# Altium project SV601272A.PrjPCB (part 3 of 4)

## Sheet SV601272A-Controller1.SchDoc: Controller
size 431 x 279 mm; Date: Not shown in title block; ApprovedBy: Not shown in title block; CheckedBy: Not shown in title block; Author: Not shown in title block; CompanyName: Not shown in title block; Engineer: Not shown in title block; Organization: Not shown in title block; Address1: Not shown in title block; Address2: Not shown in title block; Address3: Not shown in title block; Address4: Not shown in title block; DocumentNumber: 4; Revision: Use project parameter SCH_Rev; SheetNumber: 4; SheetTotal: 11; PageSetup: Record=PageOptions¦CenterHorizontal=True¦CenterVertical=True¦PrintScale=1.00¦XCorrection=1.00¦YCorrection=1.00¦PrintKind=0¦BorderSize=5000000¦LeftOffset=0¦BottomOffset=0¦Orientation=2¦PaperLength=1000¦PaperWidth=1000¦Scale=100¦PaperSource=15¦PrintQuality=600¦MediaType=1¦DitherType=10¦PaperKind=Letter¦PrintScaleMode=1
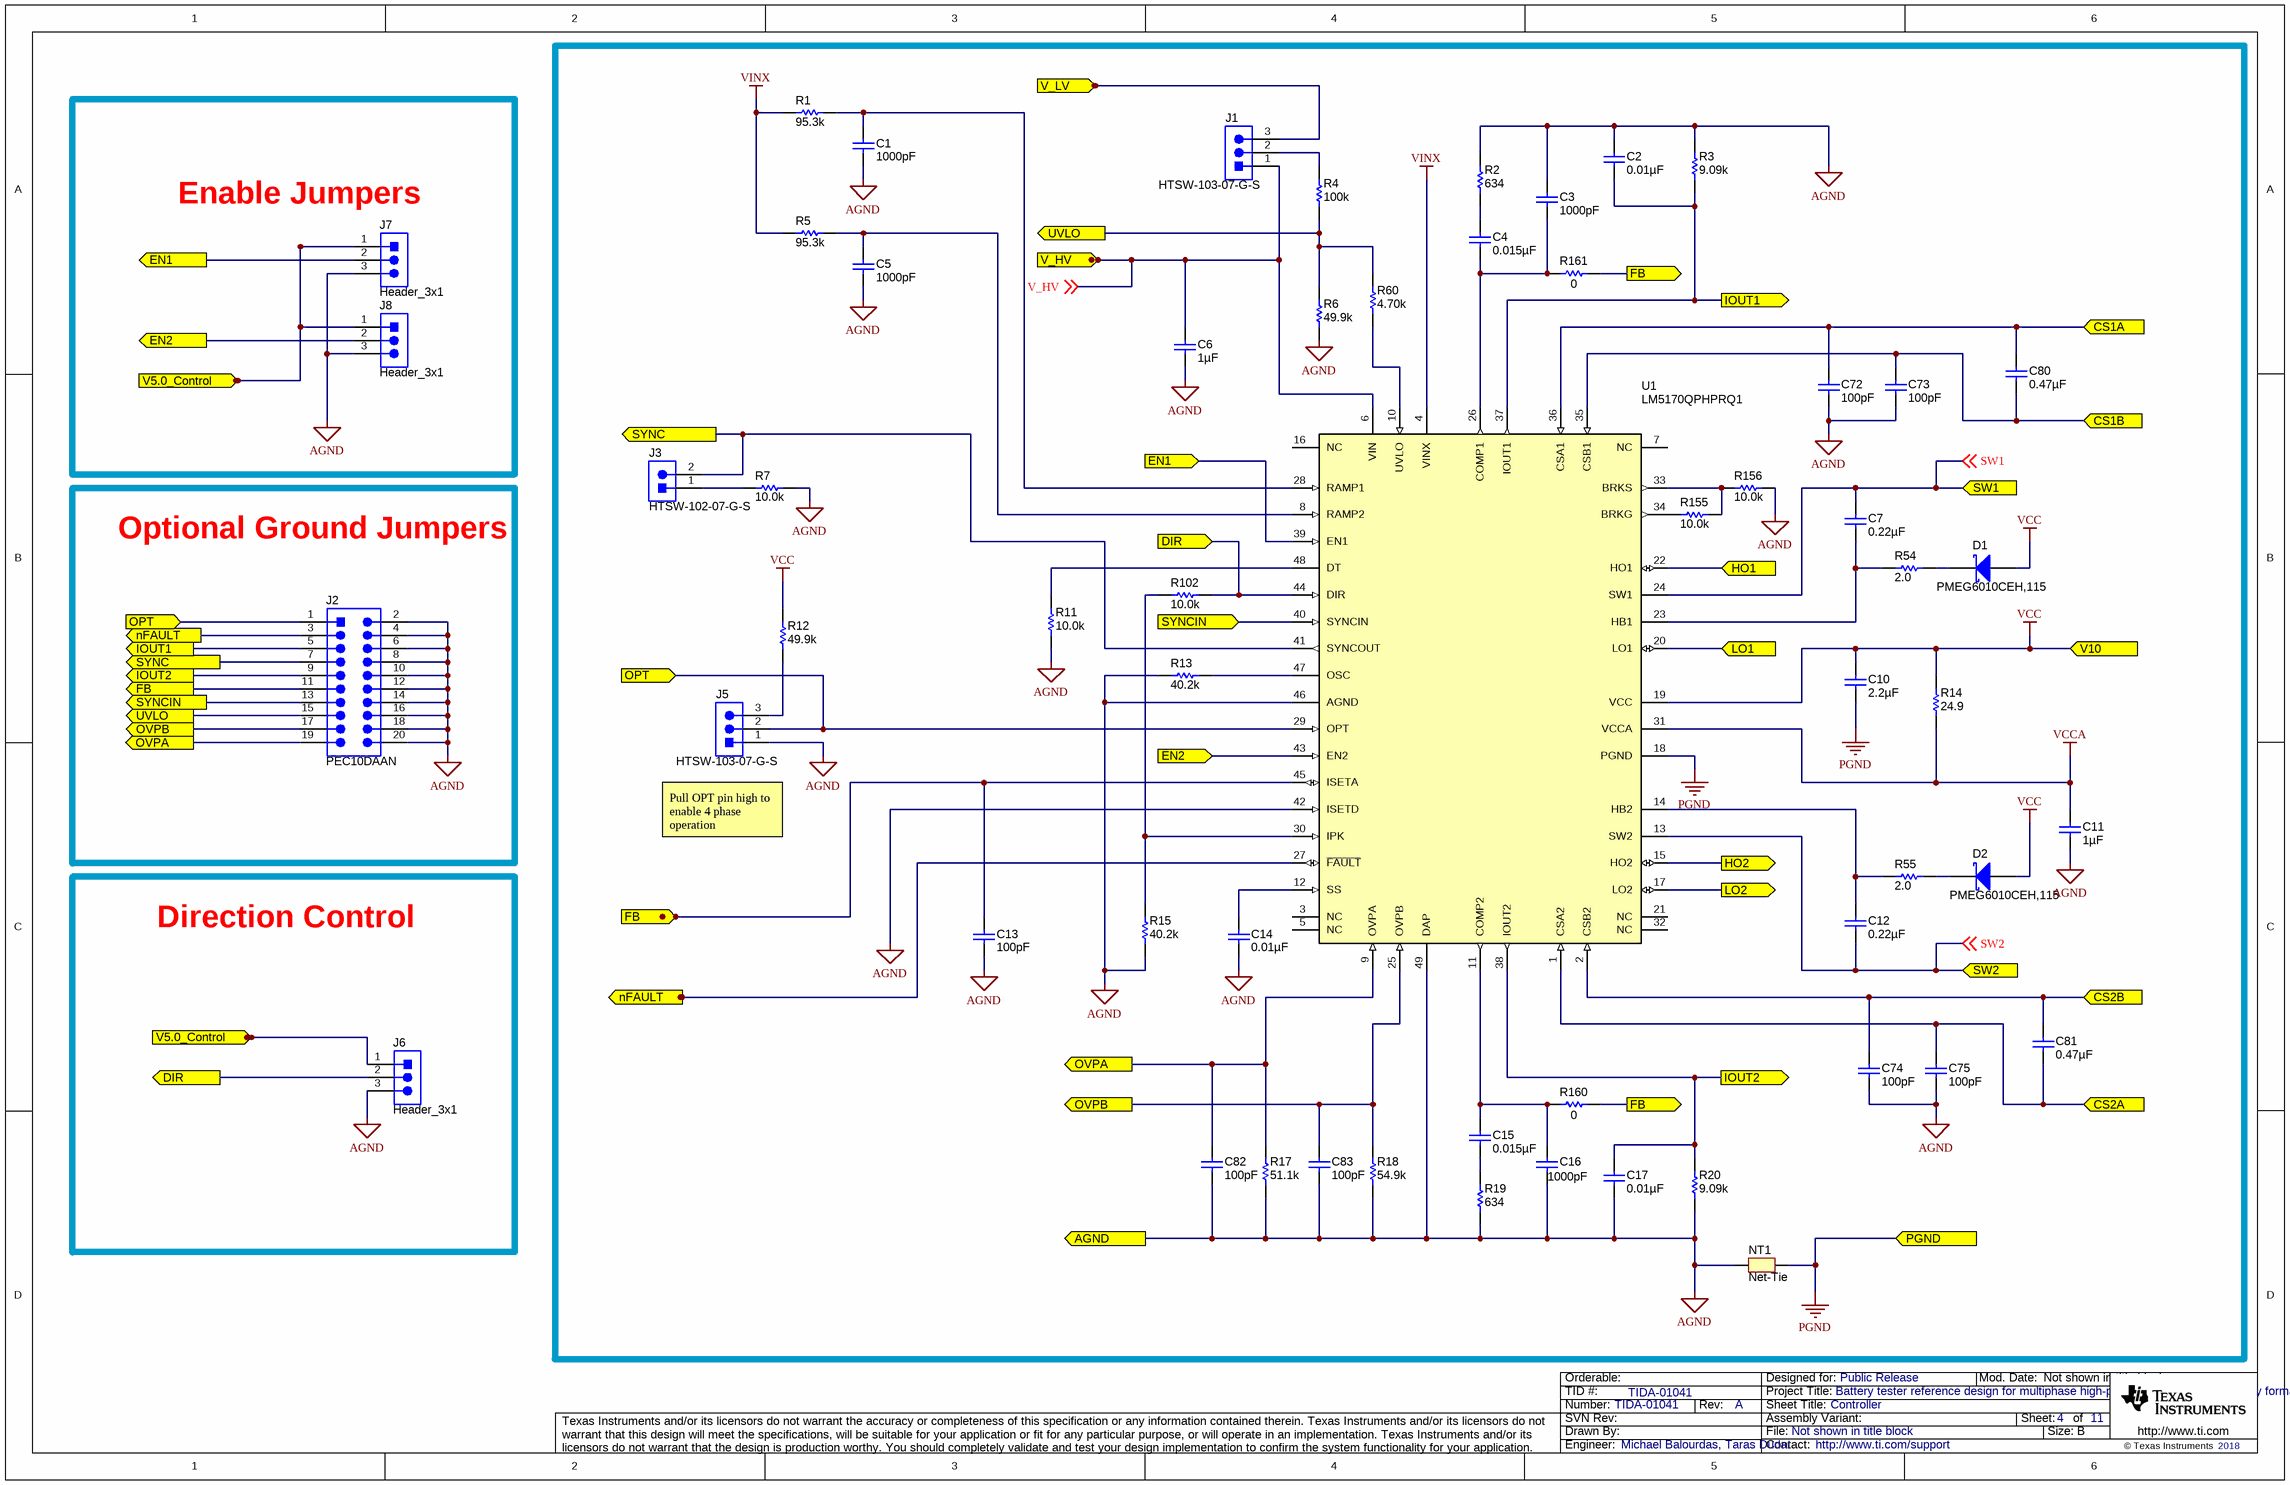
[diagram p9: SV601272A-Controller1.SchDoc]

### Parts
C1  ValueDisplayed: 1000pF  [0603L]  (hidden comment: C1608C0G2A102J080AA)
C2  ValueDisplayed: 0.01µF  [0603L]  (hidden comment: 06031C103KAT2A)
C3  ValueDisplayed: 1000pF  [0603L]  (hidden comment: C1608C0G2A102J080AA)
C4  ValueDisplayed: 0.015µF  [0603L]  (hidden comment: GRM188R71E153KA01D)
C5  ValueDisplayed: 1000pF  [0603L]  (hidden comment: C1608C0G2A102J080AA)
C6  ValueDisplayed: 1µF  [0805_HV]  (hidden comment: C2012X7S2A105K125AB)
C7  ValueDisplayed: 0.22µF  [0603L]  (hidden comment: C1608X7R1H224K080AB)
C10  ValueDisplayed: 2.2µF  [0805_HV]  (hidden comment: C2012X7R1C225K125AB)
C11  ValueDisplayed: 1µF  [0603L]  (hidden comment: GRM188R71E105KA12D)
C12  ValueDisplayed: 0.22µF  [0603L]  (hidden comment: C1608X7R1H224K080AB)
C13  ValueDisplayed: 100pF  [0603L]  (hidden comment: C0603C101J5GACTU)
C14  ValueDisplayed: 0.01µF  [0603L]  (hidden comment: 06031C103KAT2A)
C15  ValueDisplayed: 0.015µF  [0603L]  (hidden comment: GRM188R71E153KA01D)
C16  ValueDisplayed: 1000pF  [0603L]  (hidden comment: C1608C0G2A102J080AA)
C17  ValueDisplayed: 0.01µF  [0603L]  (hidden comment: 06031C103KAT2A)
C72  ValueDisplayed: 100pF  [0603L]  (hidden comment: C0603C101J5GACTU)
C73  ValueDisplayed: 100pF  [0603L]  (hidden comment: C0603C101J5GACTU)
C74  ValueDisplayed: 100pF  [0603L]  (hidden comment: C0603C101J5GACTU)
C75  ValueDisplayed: 100pF  [0603L]  (hidden comment: C0603C101J5GACTU)
C80  ValueDisplayed: 0.47µF  [0603L]  (hidden comment: GRM188R71C474KA88D)
C81  ValueDisplayed: 0.47µF  [0603L]  (hidden comment: GRM188R71C474KA88D)
C82  ValueDisplayed: 100pF  [0603L]  (hidden comment: C0603C101J5GACTU)
C83  ValueDisplayed: 100pF  [0603L]  (hidden comment: C0603C101J5GACTU)
D1  PMEG6010CEH,115  [SOD-123F]
D2  PMEG6010CEH,115  [SOD-123F]
J1  HTSW-103-07-G-S  [Samtec_HTSW-103-07-G-S]
J2  PEC10DAAN  [SULLINS_PEC10DAAN]
J3  HTSW-102-07-G-S  [Samtec_HTSW-102-07-G-S]
J5  HTSW-103-07-G-S  [Samtec_HTSW-103-07-G-S]
J6  Header_3x1  [Samtec_HTSW-103-07-G-S]
J7  Header_3x1  [Samtec_HTSW-103-07-G-S]
J8  Header_3x1  [Samtec_HTSW-103-07-G-S]
NT1  Net-Tie  [Net-Tie_10mil]  (net tie, no BOM)
R1  ValueDisplayed: 95.3k  [0603L]  (hidden comment: CRCW060395K3FKEA)
R2  ValueDisplayed: 634  [0603L]  (hidden comment: CRCW0603634RFKEA)
R3  ValueDisplayed: 9.09k  [0603L]  (hidden comment: CRCW06039K09FKEA)
R4  ValueDisplayed: 100k  [0603]  (hidden comment: CRCW0603100KFKEA)
R5  ValueDisplayed: 95.3k  [0603L]  (hidden comment: CRCW060395K3FKEA)
R6  ValueDisplayed: 49.9k  [0603]  (hidden comment: ERJ-3EKF4992V)
R7  ValueDisplayed: 10.0k  [0603L]  (hidden comment: CRCW060310K0FKEA)
R11  ValueDisplayed: 10.0k  [0603L]  (hidden comment: CRCW060310K0FKEA)
R12  ValueDisplayed: 49.9k  [0603L]  (hidden comment: CRCW060349K9FKEA)
R13  ValueDisplayed: 40.2k  [0603L]  (hidden comment: CRCW060340K2FKEA)
R14  ValueDisplayed: 24.9  [0805L]  (hidden comment: CRCW080524R9FKEA)
R15  ValueDisplayed: 40.2k  [0603]  (hidden comment: ERJ-3EKF4022V)
R17  ValueDisplayed: 51.1k  [0603L]  (hidden comment: CRCW060351K1FKEA)
R18  ValueDisplayed: 54.9k  [0603L]  (hidden comment: CRCW060354K9FKEA)
R19  ValueDisplayed: 634  [0603L]  (hidden comment: CRCW0603634RFKEA)
R20  ValueDisplayed: 9.09k  [0603L]  (hidden comment: CRCW06039K09FKEA)
R54  ValueDisplayed: 2.0  [0805_HV]  (hidden comment: CRCW08052R00JNEA)
R55  ValueDisplayed: 2.0  [0805_HV]  (hidden comment: CRCW08052R00JNEA)
R60  ValueDisplayed: 4.70k  [0603]  (hidden comment: RC0603FR-074K7L)
R102  ValueDisplayed: 10.0k  [0603L]  (hidden comment: CRCW060310K0FKEA)
R155  ValueDisplayed: 10.0k  [0603]  (hidden comment: ERJ-3EKF1002V)
R156  ValueDisplayed: 10.0k  [0603]  (hidden comment: ERJ-3EKF1002V)
R160  ValueDisplayed: 0  [0603]  (hidden comment: Resistor)
R161  ValueDisplayed: 0  [0603]  (hidden comment: Resistor)
U1  LM5170QPHPRQ1  [PHP0048D_L]

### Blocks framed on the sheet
Enable Jumpers: J7 J8
Optional Ground Jumpers: J2
Direction Control: J6

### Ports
AGND, CS1A, CS1B, CS2A, CS2B, DIR, EN1, EN2, FB, HO1, HO2, IOUT1, IOUT2, LO1, LO2, nFAULT, OPT, OVPA, OVPB, PGND, SW1, SW2, SYNC, SYNCIN, UVLO, V5.0_Control, V10, V_HV, V_LV

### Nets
AGND: C1.2 C2.1 C3.1 C5.2 C6.2 C11.2 C13.2 C14.2 C16.2 C17.2 C72.2 C73.2 C74.2 C75.2 C82.2 C83.2 J2.2 J2.4 J2.6 J2.8 J2.10 J2.12 J2.14 J2.16 J2.18 J2.20 J5.1 J6.3 J7.3 J8.3 NT1.1 R2.2 R3.2 R6.1 R7.2 R11.1 R13.1 R15.1 R17.1 R18.1 R19.1 R20.1 R156.1 U1.42(ISETD) U1.46(AGND) U1.49(DAP) ; port AGND
PGND: C10.2 NT1.2 U1.18(PGND) ; port PGND
V_HV: C6.1 J1.1 U1.6(VIN) ; off-sheet V_HV, port V_HV
V_LV: J1.3 ; port V_LV
VCC: C10.1 D1.2(A) D2.2(A) R12.2 R14.2 U1.19(VCC) ; port V10
VCCA: C11.1 R14.1 U1.31(VCCA)
VINX: R1.1 R5.1 U1.4(VINX)
CS1A: C72.1 C80.1 U1.36(CSA1) ; port CS1A
CS1B: C73.1 C80.2 U1.35(CSB1) ; port CS1B
CS2A: C75.1 C81.2 U1.1(CSA2) ; port CS2A
CS2B: C74.1 C81.1 U1.2(CSB2) ; port CS2B
DIR: J6.2 R102.2 U1.44(DIR) ; port DIR
EN: J7.2 U1.39(EN1) ; port EN1
EN2: J8.2 U1.43(EN2) ; port EN2
FB: C13.1 J2.11 R160.2 R161.2 U1.45(ISETA) ; port FB
HO1: U1.22(HO1) ; port HO1
HO2: U1.15(HO2) ; port HO2
IOUT1: C2.2 J2.5 R3.1 U1.37(IOUT1) ; port IOUT1
IOUT2: C17.1 J2.9 R20.2 U1.38(IOUT2) ; port IOUT2
LO1: U1.20(LO1) ; port LO1
LO2: U1.17(LO2) ; port LO2
nFAULT: J2.3 U1.27(~{FAULT}) ; port nFAULT
OPT: J2.1 J5.2 U1.29(OPT) ; port OPT
OVPA: C82.1 J2.19 R17.2 U1.9(OVPA) ; port OVPA
OVPB: C83.1 J2.17 R18.2 U1.25(OVPB) ; port OVPB
SW1: C7.1 U1.24(SW1) ; off-sheet SW1, port SW1
SW2: C12.2 U1.13(SW2) ; off-sheet SW2, port SW2
SYNC: J2.7 J3.2 U1.41(SYNCOUT) ; port SYNC
SYNCIN: J2.13 U1.40(SYNCIN) ; port SYNCIN
UVLO: J2.15 R4.1 R6.2 R60.2 ; port UVLO
V5.0_Control: J6.1 J7.1 J8.1 ; port V5.0_Control
NetC1_1: C1.1 R1.2 U1.28(RAMP1)
NetC3_2: C3.2 C4.2 R161.1 U1.26(COMP1)
NetC4_1: C4.1 R2.1
NetC5_1: C5.1 R5.2 U1.8(RAMP2)
NetC7_2: C7.2 R54.1 U1.23(HB1)
NetC12_1: C12.1 R55.1 U1.14(HB2)
NetC14_1: C14.1 U1.12(SS)
NetC15_1: C15.1 C16.1 R160.1 U1.11(COMP2)
NetC15_2: C15.2 R19.2
NetD1_1: D1.1(K) R54.2
NetD2_1: D2.1(K) R55.2
NetJ1_2: J1.2 R4.2
NetJ3_1: J3.1 R7.1
NetJ5_3: J5.3 R12.1
NetR11_2: R11.2 U1.48(DT)
NetR13_2: R13.2 U1.47(OSC)
NetR15_2: R15.2 R102.1 U1.30(IPK)
NetR60_1: R60.1 U1.10(UVLO)
NetR155_1: R155.1 R156.2 U1.33(BRKS)
NetR155_2: R155.2 U1.34(BRKG)

Not connected (* = marked no-connect by the designer): U1 3(NC) 5(NC) 7(NC) 16(NC) 21(NC) 32(NC)

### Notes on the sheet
- (near J5) Pull OPT pin high to enable 4 phase operation

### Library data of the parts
C1 C3 C5 C16 = C1608C0G2A102J080AA: CAP, CERM, 1000 pF, 100 V, +/- 5%, C0G/NP0, 0603; Manufacturer: TDK; Polarized: N; CompType: Capacitor; Value: 1000pF; U/M: EA; Cap_F: 0.000000001; Tolerance_%: 5; ESR_ohm: 0.0589; Value1: 0.0589 ohm; VDC_V: 100; Value2: 100V; TaMin_C: -55; TaMax_C: 125; Cap_Case: 0603; AEC Category: Q200
C2 C14 C17 = 06031C103KAT2A: CAP, CERM, 0.01 µF, 100 V, +/- 10%, X7R, 0603; Manufacturer: AVX; Polarized: N; CompType: Capacitor; Value: 0.01uF; U/M: EA; Cap_F: 0.00000001; Tolerance_%: 10; ESR_ohm: 0.098; Value1: 0.098 ohm; VDC_V: 100; Value2: 100V; TaMin_C: -55; TaMax_C: 125; Cap_Case: 0603
C4 C15 = GRM188R71E153KA01D: CAP, CERM, 0.015 µF, 25 V, +/- 10%, X7R, 0603; Manufacturer: MuRata; Polarized: N; CompType: Capacitor; Value: 0.015uF; U/M: EA; Cap_F: 0.000000015; Tolerance_%: 10; Value1: Unknown; VDC_V: 25; Value2: 25V; TaMin_C: -55; TaMax_C: 125; Cap_Case: 0603
C6 = C2012X7S2A105K125AB: CAP, CERM, 1 µF, 100 V, +/- 10%, X7S, 0805; Manufacturer: TDK; Polarized: N; CompType: Capacitor; Value: 1uF; U/M: EA; Cap_F: 0.000001; Tolerance_%: 10; Value1: Unknown; VDC_V: 100; Value2: 100V; TaMin_C: -55; TaMax_C: 125; Cap_Case: 0805; AEC Category: Q200
C7 C12 = C1608X7R1H224K080AB: CAP, CERM, 0.22 µF, 50 V, +/- 10%, X7R, 0603; Manufacturer: TDK; Polarized: N; CompType: Capacitor; Value: 0.22uF; U/M: EA; Cap_F: 0.00000022; Tolerance_%: 10; Value1: Unknown; VDC_V: 50; Value2: 50V; TaMin_C: -55; TaMax_C: 125; Cap_Case: 0603
C10 = C2012X7R1C225K125AB: CAP, CERM, 2.2 µF, 16 V, +/- 10%, X7R, 0805; Manufacturer: TDK; CompType: Capacitor; Value: 2.2uF; U/M: EA; Tolerance_%: 10; VDC_V: 16; Polarized: N; Cap_F: 0.0000022; ESR_ohm: 0.0049; Value1: 0.0049 ohm; Value2: 16V; TaMin_C: -55; TaMax_C: 125; Cap_Case: 0805; AEC Category: Q200
C11 = GRM188R71E105KA12D: CAP, CERM, 1 µF, 25 V, +/- 10%, X7R, 0603; Manufacturer: MuRata; Polarized: N; CompType: Capacitor; Value: 1uF; U/M: EA; Cap_F: 0.000001; Tolerance_%: 10; Value1: Unknown; VDC_V: 25; Value2: 25V; TaMin_C: -55; TaMax_C: 125; Cap_Case: 0603
C13 = C0603C101J5GACTU: CAP, CERM, 100 pF, 50 V, +/- 5%, C0G/NP0, 0603; Manufacturer: Kemet; Polarized: N; CompType: Capacitor; Value: 100pF; U/M: EA; Cap_F: 0.0000000001; Tolerance_%: 5; Value1: Unknown; VDC_V: 50; Value2: 50V; TaMin_C: -55; TaMax_C: 125; Cap_Case: 0603; AEC Category: Q200; SizeArea_mm2: 1.28; SizeAreaWB_mm2: 4.68; SizeX_mm: 1.6; SizeY_mm: 0.8; SizeZ_mm: 1
C72-C75 C82 C83 = C0603C101J5GACTU: CAP, CERM, 100 pF, 50 V, +/- 5%, C0G/NP0, 0603; Manufacturer: Kemet; Polarized: N; CompType: Capacitor; Value: 100pF; U/M: EA; Cap_F: 0.0000000001; Tolerance_%: 5; Value1: Unknown; VDC_V: 50; Value2: 50V; TaMin_C: -55; TaMax_C: 125; Cap_Case: 0603; AEC Category: Q200
C80 C81 = GRM188R71C474KA88D: CAP, CERM, 0.47 µF, 16 V, +/- 10%, X7R, 0603; Manufacturer: MuRata; Polarized: N; CompType: Capacitor; Value: 0.47uF; U/M: EA; Cap_F: 0.00000047; Tolerance_%: 10; Value1: Unknown; VDC_V: 16; Value2: 16V; TaMin_C: -55; TaMax_C: 125; Cap_Case: 0603; AEC Category: Q200
D1 D2 = PMEG6010CEH,115: Diode, Schottky, 60 V, 1 A, SOD-123F; Manufacturer: NXP Semiconductor; U/M: EA; Vf_V: 0.57; Value: 60V; Value1: 1A; Value2: 0.57V; Io_A: 1; Vr_V: 60; TJmax_C: 150
J1 J5 = HTSW-103-07-G-S: Header, 100mil, 3x1, Gold, TH; Manufacturer: Samtec; SymbolCreator: a0799628; U/M: EA
J2 = CMP-0054623-1: Header, 2.54mm, 10x2, Tin, TH; Manufacturer: Sullins Connector Solutions; CNHeader: TRUE; Current_A: 3A; Green_Lifecycle: Not Set; Shrouded: N; Gender: Male; Green_REACh: Incomplete; Row_Count: 2; RowSpacing_mm: 2.54; CT: FALSE; Cert_UL: Y
J3 = HTSW-102-07-G-S: Header, 100mil, 2x1, Gold, TH; Manufacturer: Samtec; SymbolCreator: a0412235; U/M: EA
J6-J8 = CMP-0075484-1: Header, 100mil, 3x1, Gold, TH; PartNumber: HTSW-103-07-G-S; Manufacturer: Samtec; CNHeader: True; CT: False; Green_Lifecycle: Active; Green_REACh: Passed
NT1 = Net-Tie: Single point connection between nets.; SymbolCreator: codlsc
R1 R5 = CRCW060395K3FKEA: RES, 95.3 k, 1%, 0.1 W, 0603; Manufacturer: Vishay-Dale; CompType: Resistor; Value: 95.3k; Res_ohm: 95300; Value_Code: 95k3; Tolerance_%: 1; Power_W: 0.1; Value2: 0.1W; VDC_V: 75; TempCo: 100 ppm/C; EIA_Code: E96; U/M: EA
R2 R19 = CRCW0603634RFKEA: RES, 634, 1%, 0.1 W, 0603; Manufacturer: Vishay-Dale; CompType: Resistor; Value: 634; Value_Code: 634R; Tolerance_%: 1; Power_W: 0.1; Value2: 0.1W; VDC_V: 75; TempCo: 100 ppm/C; EIA_Code: E96; U/M: EA
R3 R20 = CRCW06039K09FKEA: RES, 9.09 k, 1%, 0.1 W, 0603; Manufacturer: Vishay-Dale; CompType: Resistor; Value: 9.09k; Res_ohm: 9090; Value_Code: 9k09; Tolerance_%: 1; Power_W: 0.1; Value2: 0.1W; VDC_V: 75; TempCo: 100 ppm/C; EIA_Code: E96; U/M: EA
R4 = CMP-0021990-4: RES, 100 k, 1%, 0.1 W, AEC-Q200 Grade 0, 0603; Manufacturer: Vishay-Dale; Power_W: 100mW; TempCo: 100 ppm/C; Value: 100k; EIA_Code: E96; SizeX_mm: 1.6; SizeY_mm: 0.8; SizeZ_mm: 1; Value2: 0.1W; SizeArea_mm2: 1.28; CompType: Resistor; AEC Qualified: Y; VDC_V: 75V; AEC Category: Q200; AEC Grade: 0
R6 = CMP-0022705-3: RES, 49.9 k, 1%, 0.1 W, AEC-Q200 Grade 0, 0603; Manufacturer: Panasonic; Power_W: 100mW; TempCo: 100 ppm/C; Value_Code: 49k9; U/M: EA; Value: 49.9k; EIA_Code: E96; SizeX_mm: 1.6; SizeY_mm: 0.8; SizeZ_mm: 1; Value2: 0.1W; SizeArea_mm2: 1.28; CompType: Resistor; AEC Qualified: Y; VDC_V: 75V; AEC Grade: 0; AEC Category: Q200
R7 R102 = CRCW060310K0FKEA: RES, 10.0 k, 1%, 0.1 W, 0603; Manufacturer: Vishay-Dale; CompType: Resistor; Value: 10.0k; Res_ohm: 10000; Value_Code: 10k0; Tolerance_%: 1; Power_W: 0.1; Value2: 0.1W; VDC_V: 75; TempCo: 100 ppm/C; EIA_Code: E96; U/M: EA
R11 = CRCW060310K0FKEA: RES, 10.0 k, 1%, 0.1 W, 0603; Manufacturer: Vishay-Dale; CompType: Resistor; Value: 10.0k; Res_ohm: 10000; Value_Code: 10k0; Tolerance_%: 1; Power_W: 0.1; Value2: 0.1W; VDC_V: 75; TempCo: 100 ppm/C; EIA_Code: E96; U/M: EA; SizeArea_mm2: 1.28; SizeX_mm: 1.6; SizeY_mm: 0.8; AEC Category: Q200
R12 = CRCW060349K9FKEA: RES, 49.9 k, 1%, 0.1 W, 0603; Manufacturer: Vishay-Dale; CompType: Resistor; Value: 49.9k; Res_ohm: 49900; Value_Code: 49k9; Tolerance_%: 1; Power_W: 0.1; Value2: 0.1W; VDC_V: 75; TempCo: 100 ppm/C; EIA_Code: E96; U/M: EA
R13 = CRCW060340K2FKEA: RES, 40.2 k, 1%, 0.1 W, 0603; Manufacturer: Vishay-Dale; CompType: Resistor; Value: 40.2k; Res_ohm: 40200; Value_Code: 40k2; Tolerance_%: 1; Power_W: 0.1; Value2: 0.1W; VDC_V: 75; TempCo: 100 ppm/C; EIA_Code: E96; U/M: EA; SizeArea_mm2: 1.28; SizeX_mm: 1.6; SizeY_mm: 0.8; AEC Category: Q200
R14 = CRCW080524R9FKEA: RES, 24.9, 1%, 0.125 W, 0805; Manufacturer: Vishay-Dale; CompType: Resistor; Value: 24.9; Value_Code: 24R9; Tolerance_%: 1; Power_W: 0.125; Value2: 0.125W; VDC_V: 150; TempCo: 100 ppm/C; EIA_Code: E96; U/M: EA
R15 = CMP-0022700-3: RES, 40.2 k, 1%, 0.1 W, AEC-Q200 Grade 0, 0603; Manufacturer: Panasonic; Power_W: 100mW; TempCo: 100 ppm/C; Value_Code: 40k2; U/M: EA; Value: 40.2k; EIA_Code: E96; SizeX_mm: 1.6; SizeY_mm: 0.8; SizeZ_mm: 1; Value2: 0.1W; SizeArea_mm2: 1.28; CompType: Resistor; AEC Qualified: Y; VDC_V: 75V; AEC Grade: 0; AEC Category: Q200
R17 = CRCW060351K1FKEA: RES, 51.1 k, 1%, 0.1 W, 0603; Manufacturer: Vishay-Dale; CompType: Resistor; Value: 51.1k; Res_ohm: 51100; Value_Code: 51k1; Tolerance_%: 1; Power_W: 0.1; Value2: 0.1W; VDC_V: 75; TempCo: 100 ppm/C; EIA_Code: E96; U/M: EA
R18 = CRCW060354K9FKEA: RES, 54.9 k, 1%, 0.1 W, 0603; Manufacturer: Vishay-Dale; CompType: Resistor; Value: 54.9k; Res_ohm: 54900; Value_Code: 54k9; Tolerance_%: 1; Power_W: 0.1; Value2: 0.1W; VDC_V: 75; TempCo: 100 ppm/C; EIA_Code: E96; U/M: EA
R54 R55 = CRCW08052R00JNEA: RES, 2.0, 5%, 0.125 W, 0805; Manufacturer: Vishay-Dale; CompType: Resistor; Value: 2.0; Res_ohm: 2; Value_Code: 2R00; Tolerance_%: 5; Power_W: 0.125; Value2: 0.125W; VDC_V: 150; TempCo: 200 ppm/C; EIA_Code: E24; U/M: EA; AEC Category: Q200
R60 = CMP-0023153-3: RES, 4.70 k, 1%, 0.1 W, 0603; Manufacturer: Yageo America; Power_W: 100mW; TempCo: 200 ppm/C; Value_Code: 4k70; U/M: EA; Value: 4.70k; Res_ohm: 4.7k; SizeX_mm: 1.6; SizeY_mm: 0.8; SizeZ_mm: 1; Value2: 0.1W; SizeArea_mm2: 1.28; CompType: Resistor; VDC_V: 150V; AEC Category: Q200
R155 R156 = CMP-0022684-3: RES, 10.0 k, 1%, 0.1 W, 0603; Manufacturer: Panasonic; Power_W: 100mW; TempCo: 100 ppm/C; Value_Code: 10k0; U/M: EA; Value: 10.0k; EIA_Code: E96; Res_ohm: 10k; SizeX_mm: 1.6; SizeY_mm: 0.8; SizeZ_mm: 1; Value2: 0.1W; SizeArea_mm2: 1.28; CompType: Resistor; VDC_V: 75V; AEC Category: Q200
R160 R161 = CMP-0025874-3: RES, 0, 5%, 0.1 W, 0603; PartNumber: ERJ-3GEY0R00V; Manufacturer: Panasonic; Value: 0; Value_Code: 0000; Power_W: 100mW; Value2: 0.1W; VDC_V: 50V; TempCo: 600 ppm/C; EIA_Code: E24; U/M: EA; AEC Category: Q200; SizeArea_mm2: 1.28; SizeX_mm: 1.6; SizeY_mm: 0.8; SizeZ_mm: 1
U1 = LM5170QPHPRQ1: Dual Channel 48V-12V Bidirectional Current Controller, PHP0048D; Manufacturer: Texas Instruments; Alternate PartNumber: LM5170QPHPTQ1; SymbolCreator: Altium; CompType: IC; U/M: EA

## Sheet SV601272A-Bias.SchDoc: Bias Supply
size 431 x 279 mm; Date: Not shown in title block; ApprovedBy: Not shown in title block; CheckedBy: Not shown in title block; Author: Not shown in title block; CompanyName: Not shown in title block; Engineer: Not shown in title block; Organization: Not shown in title block; Address1: Not shown in title block; Address2: Not shown in title block; Address3: Not shown in title block; Address4: Not shown in title block; DocumentNumber: 3; Revision: Use project parameter SCH_Rev; SheetNumber: 3; SheetTotal: 11; PageSetup: Record=PageOptions¦CenterHorizontal=True¦CenterVertical=True¦PrintScale=1.00¦XCorrection=1.00¦YCorrection=1.00¦PrintKind=0¦BorderSize=5000000¦LeftOffset=0¦BottomOffset=0¦Orientation=2¦PaperLength=1000¦PaperWidth=1000¦Scale=100¦PaperSource=15¦PrintQuality=600¦MediaType=1¦DitherType=10¦PaperKind=Letter¦PrintScaleMode=1
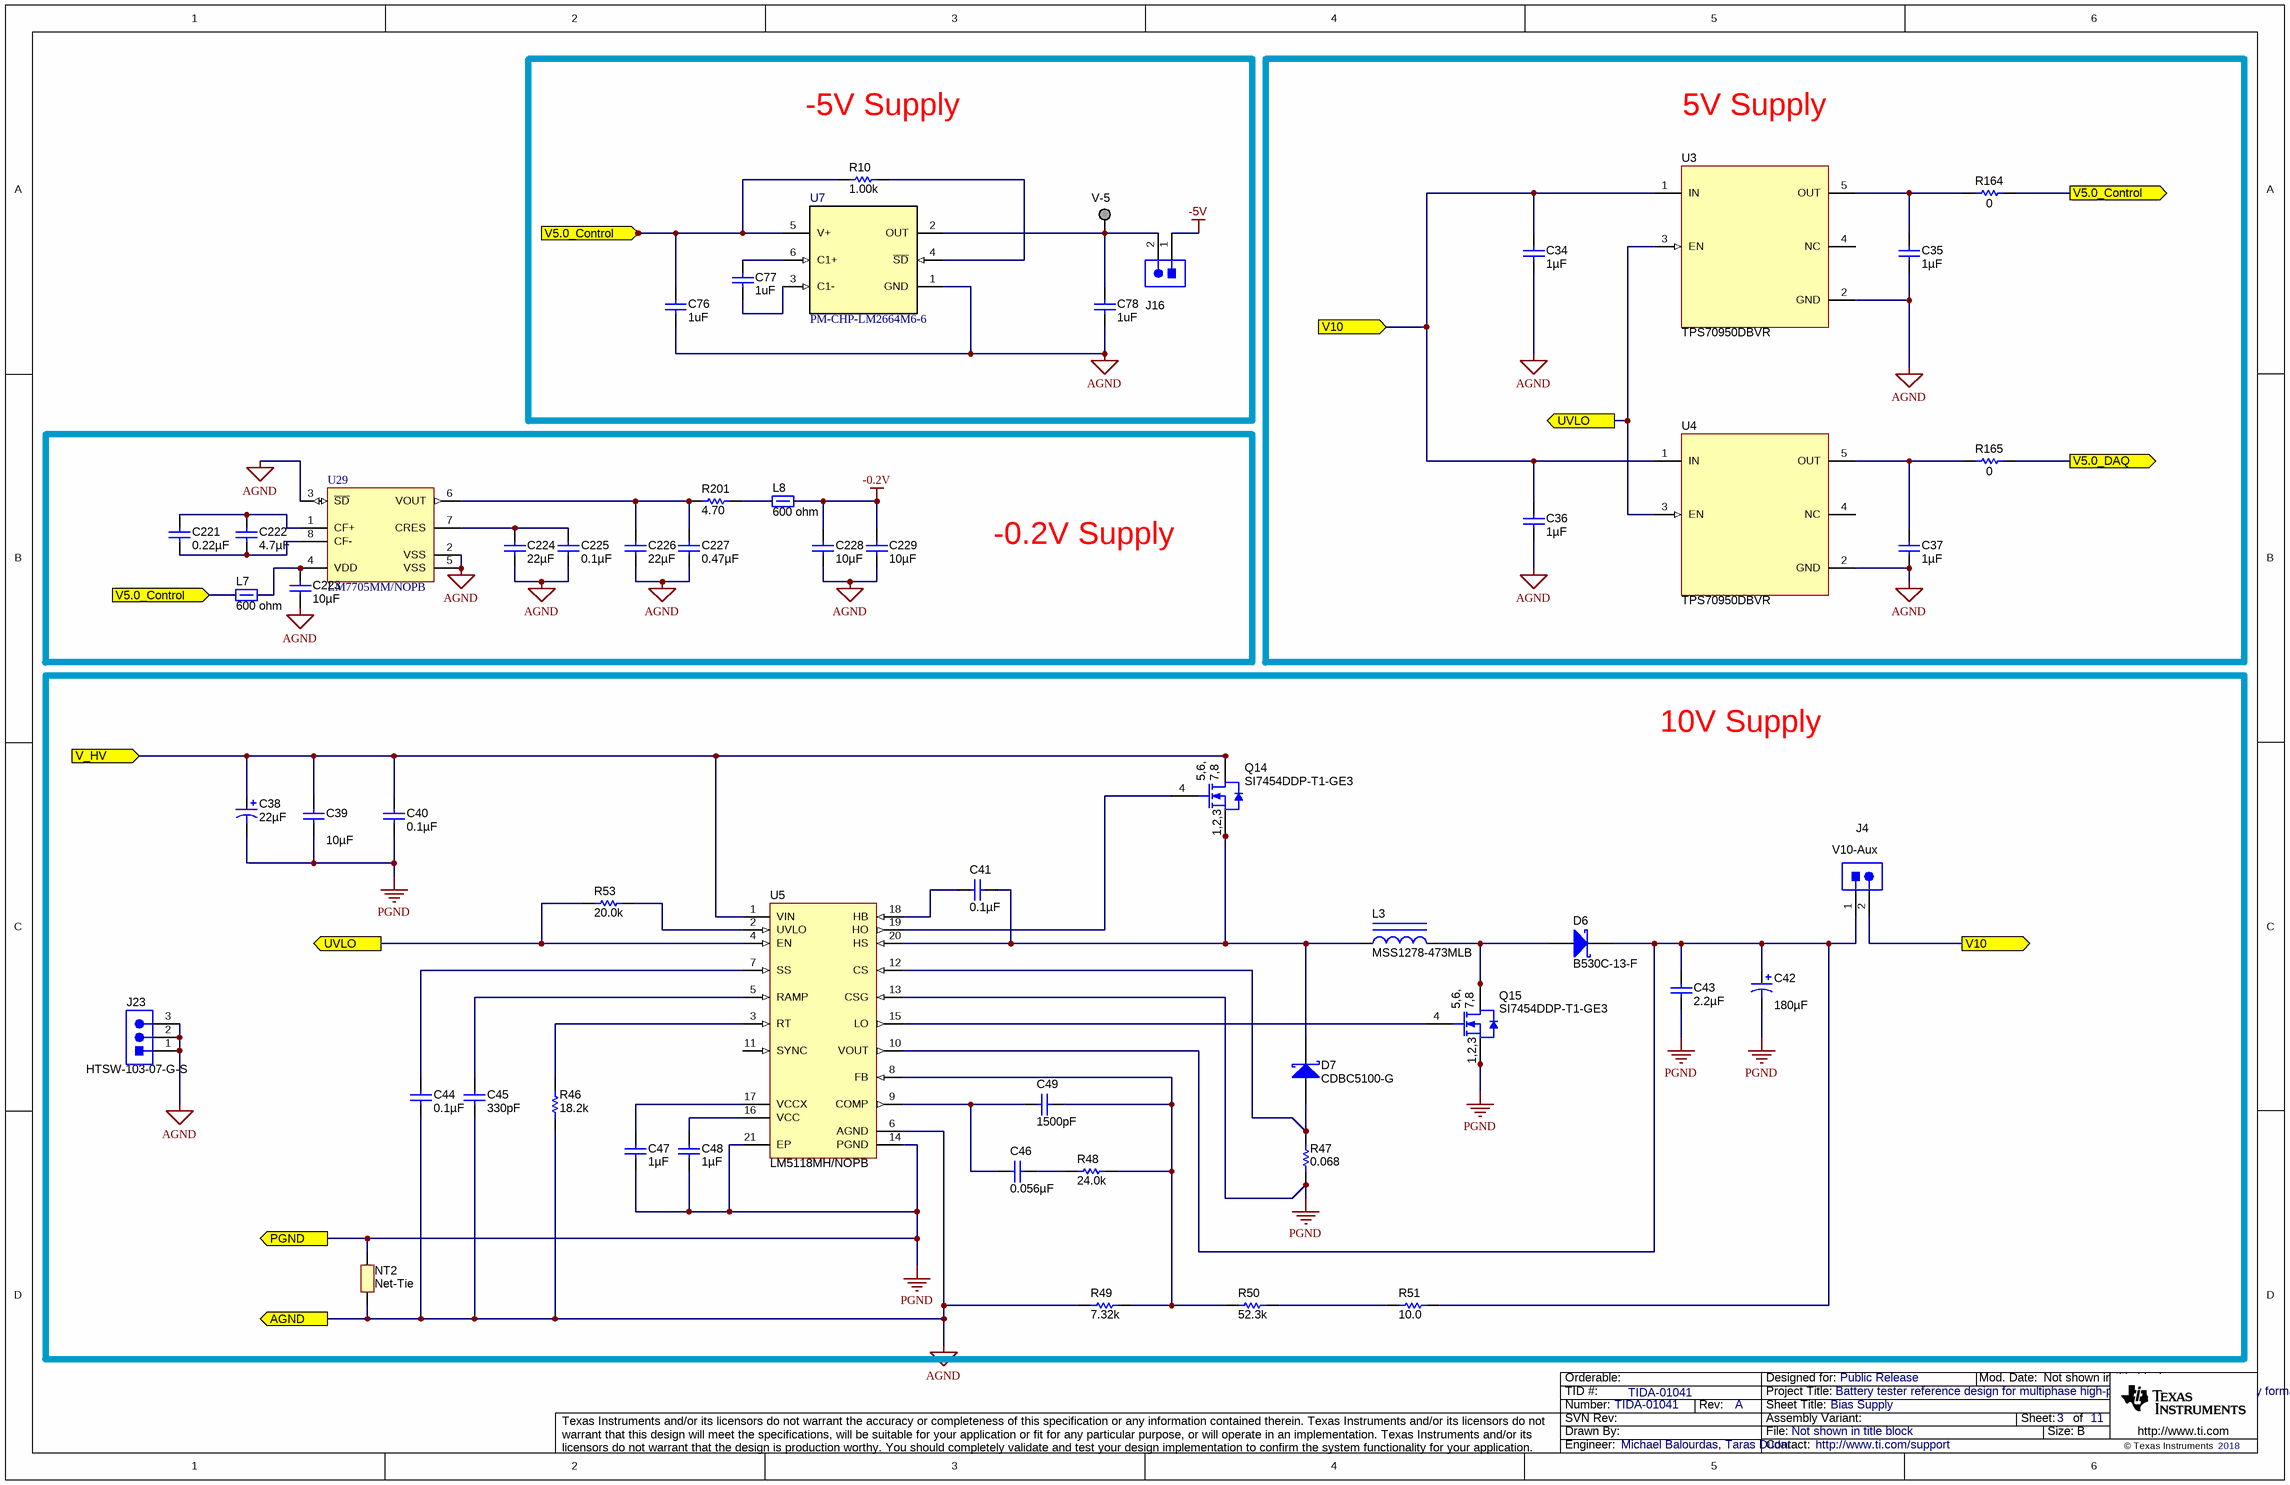
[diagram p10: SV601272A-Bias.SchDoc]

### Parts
C34  ValueDisplayed: 1µF  [0805_HV]  (hidden comment: C2012X7S2A105K125AB)
C35  ValueDisplayed: 1µF  [0805_HV]  (hidden comment: C2012X7S2A105K125AB)
C36  ValueDisplayed: 1µF  [0805_HV]  (hidden comment: C2012X7S2A105K125AB)
C37  ValueDisplayed: 1µF  [0805_HV]  (hidden comment: C2012X7S2A105K125AB)
C38  ValueDisplayed: 22µF  [CAPSMT_62_JA0]  (hidden comment: EMVH101ADA220MJA0G)
C39  ValueDisplayed: 10µF  [2220_250]  (hidden comment: C5750X7S2A106M230KB)
C40  ValueDisplayed: 0.1µF  [0805_HV]  (hidden comment: C2012X7R2A104K125AA)
C41  ValueDisplayed: 0.1µF  [0603L]  (hidden comment: GRM188R72A104KA35D)
C42  ValueDisplayed: 180µF  [CAPSMT_62_HC0]  (hidden comment: APXA160ARA181MHC0G)
C43  ValueDisplayed: 2.2µF  [0805_HV]  (hidden comment: C2012X7R1C225K125AB)
C44  ValueDisplayed: 0.1µF  [0603L]  (hidden comment: GRM188R72A104KA35D)
C45  ValueDisplayed: 330pF  [0603L]  (hidden comment: C1608C0G2A331J080AA)
C46  ValueDisplayed: 0.056µF  [0603L]  (hidden comment: GRM188R71H563KA93D)
C47  ValueDisplayed: 1µF  [0603L]  (hidden comment: GRM188R71E105KA12D)
C48  ValueDisplayed: 1µF  [0603L]  (hidden comment: GRM188R71E105KA12D)
C49  ValueDisplayed: 1500pF  [0603L]  (hidden comment: GRM1885C2A152JA01D)
C76  ValueDisplayed: 1uF  [0805_HV]  (hidden comment: Capacitor)
C77  ValueDisplayed: 1uF  [0805_HV]  (hidden comment: Capacitor)
C78  ValueDisplayed: 1uF  [0805_HV]  (hidden comment: Capacitor)
C221  ValueDisplayed: 0.22µF  [0603]  (hidden comment: GRM188R61A224KA01D)
C222  ValueDisplayed: 4.7µF  [0603]  (hidden comment: GRM188R61A475MAAJ)
C223  ValueDisplayed: 10µF  [0603]  (hidden comment: GRM188R61A106ME69D)
C224  ValueDisplayed: 22µF  [0603]  (hidden comment: GRM188R60J226MEA0D)
C225  ValueDisplayed: 0.1µF  [0603]  (hidden comment: GRM188R61C104KA01D)
C226  ValueDisplayed: 22µF  [0603]  (hidden comment: GRM188R60J226MEA0D)
C227  ValueDisplayed: 0.47µF  [0603]  (hidden comment: GRM188R71E474KA12D)
C228  ValueDisplayed: 10µF  [0603]  (hidden comment: GRM188R61A106ME69D)
C229  ValueDisplayed: 10µF  [0603]  (hidden comment: GRM188R61A106ME69D)
D6  B530C-13-F  [SMC]
D7  CDBC5100-G  [SMC]
J4  HTSW-102-07-G-S  [Samtec_HTSW-102-07-G-S]  (value not drawn)
J16  HTSW-102-07-G-S  [Samtec_HTSW-102-07-G-S]  (value not drawn)
J23  HTSW-103-07-G-S  [Samtec_HTSW-103-07-G-S]
L3  MSS1278-473MLB  [mss1278]
L7  value 600 ohm  [0805_HV]  (hidden comment: MPZ2012S601A)
L8  value 600 ohm  [0805_HV]  (hidden comment: MPZ2012S601A)
NT2  Net-Tie  [Net-Tie_10mil]  (net tie, no BOM)
Q14  SI7454DDP-T1-GE3  [PowerPAK_SO-8]
Q15  SI7454DDP-T1-GE3  [PowerPAK_SO-8]
R10  ValueDisplayed: 1.00k  [0603]  (hidden comment: ERJ-3EKF1001V)
R46  ValueDisplayed: 18.2k  [0603L]  (hidden comment: CRCW060318K2FKEA)
R47  ValueDisplayed: 0.068  [0612]  (hidden comment: PRL1632-R068-F-T1)
R48  ValueDisplayed: 24.0k  [0603L]  (hidden comment: RC0603FR-0724KL)
R49  ValueDisplayed: 7.32k  [0603]  (hidden comment: RC0603FR-077K32L)
R50  ValueDisplayed: 52.3k  [0603]  (hidden comment: RC0603FR-0752K3L)
R51  ValueDisplayed: 10.0  [0603L]  (hidden comment: CRCW060310R0FKEA)
R53  ValueDisplayed: 20.0k  [0603L]  (hidden comment: CRCW060320K0FKEA)
R164  ValueDisplayed: 0  [0603]  (hidden comment: Resistor)
R165  ValueDisplayed: 0  [0603]  (hidden comment: Resistor)
R201  ValueDisplayed: 4.70  [0603]  (hidden comment: RT0603DRE074R7L)
U3  TPS70950DBVR  [DBV0005A_N]
U4  TPS70950DBVR  [DBV0005A_N]
U5  LM5118MH/NOPB  [MXA20A_N]
U7  PM-CHP-LM2664M6-6  [DBV0006A_M]
U29  LM7705MM/NOPB  [MUA08A_N]
V-5  Pogo Pad  [PogoPad]  (value not drawn)  (no BOM)

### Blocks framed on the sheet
V10-Aux: C38-C49 D6 D7 J4 J23 L3 NT2 Q14 Q15 R46-R51 R53 U5

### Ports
AGND, PGND, UVLO, V5.0_Control, V5.0_DAQ, V10, V_HV

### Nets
-0.2V: C228.1 C229.1 L8.1
-5V: J16.1
AGND: C34.2 C35.2 C36.2 C37.2 C44.2 C45.2 C76.2 C78.2 C223.2 C224.2 C225.2 C226.2 C227.2 C228.2 C229.2 J23.1 J23.2 J23.3 NT2.1 R46.1 R49.1 U3.2(GND) U4.2(GND) U5.6(AGND) U7.1(GND) U29.2(VSS) U29.3(~{SD}) U29.5(VSS) ; port AGND
AVDD: R165.2 ; port V5.0_DAQ
PGND: C38.2(-) C39.2 C40.2 C42.2(-) C43.2 C47.2 C48.2 NT2.2 Q15.1(S) Q15.2(S) Q15.3(S) R47.1 U5.13(CSG) U5.14(PGND) U5.21(EP) ; port PGND
V_HV: C38.1(+) C39.1 C40.1 Q14.5(D) Q14.6(D) Q14.7(D) Q14.8(D) Q14.9(D) U5.1(VIN) ; port V_HV
VCC: C34.1 C36.1 J4.2 U3.1(IN) U4.1(IN) ; port V10
UVLO: R53.1 U3.3(EN) U4.3(EN) U5.4(EN) ; port UVLO
V5.0_Control: C76.1 L7.2 R10.1 R164.2 U7.5(V+) ; port V5.0_Control
NetC35_1: C35.1 R164.1 U3.5(OUT)
NetC37_1: C37.1 R165.1 U4.5(OUT)
NetC41_1: C41.1 D7.1(K) L3.1 Q14.1(S) Q14.2(S) Q14.3(S) U5.20(HS)
NetC41_2: C41.2 U5.18(HB)
NetC42_1: C42.1(+) C43.1 D6.1(K) J4.1 R51.2 U5.10(VOUT)
NetC44_1: C44.1 U5.7(SS)
NetC45_1: C45.1 U5.5(RAMP)
NetC46_1: C46.1 C49.1 U5.9(COMP)
NetC46_2: C46.2 R48.2
NetC47_1: C47.1 U5.17(VCCX)
NetC48_1: C48.1 U5.16(VCC)
NetC49_2: C49.2 R48.1 R49.2 R50.1 U5.8(FB)
NetC77_1: C77.1 U7.6(C1+)
NetC77_2: C77.2 U7.3(C1-)
NetC78_1: C78.1 J16.2 U7.2(OUT) V-5.1
NetC221_1: C221.1 C222.1 U29.1(CF+)
NetC221_2: C221.2 C222.2 U29.8(CF-)
NetC223_1: C223.1 L7.1 U29.4(VDD)
NetC224_1: C224.1 C225.1 U29.7(CRES)
NetC226_1: C226.1 C227.1 R201.1 U29.6(VOUT)
NetD6_2: D6.2(A) L3.2 Q15.5(D) Q15.6(D) Q15.7(D) Q15.8(D) Q15.9(D)
NetD7_2: D7.2(A) R47.2 U5.12(CS)
NetL8_2: L8.2 R201.2
NetQ14_4: Q14.4(G) U5.19(HO)
NetQ15_4: Q15.4(G) U5.15(LO)
NetR10_2: R10.2 U7.4(~{SD})
NetR46_2: R46.2 U5.3(RT)
NetR50_2: R50.2 R51.1
NetR53_2: R53.2 U5.2(UVLO)

Not connected (* = marked no-connect by the designer): U3 4(NC); U4 4(NC); U5 11(SYNC)

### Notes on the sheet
- -5V Supply
- 5V Supply
- -0.2V Supply
- 10V Supply

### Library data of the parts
C34-C37 = C2012X7S2A105K125AB: as C6 on sheet SV601272A-Controller1
C38 = EMVH101ADA220MJA0G: CAP, AL, 22 µF, 100 V, +/- 20%, 0.55 ohm, SMD; Manufacturer: Chemi-Con; Polarized: Y; CompType: Capacitor; Value: 22uF; U/M: EA; Cap_F: 0.000022; Tolerance_%: 20; VDC_V: 100; Value2: 100V; ESR_ohm: 0.55; IRMS_A: 0.115; TaMin_C: -40; TaMax_C: 125; Cap_Case: JA0
C39 = C5750X7S2A106M230KB: CAP, CERM, 10 µF, 100 V, +/- 20%, X7S,; Manufacturer: TDK; Polarized: N; CompType: Capacitor; Value: 10uF; U/M: EA; Cap_F: 0.00001; Tolerance_%: 20; ESR_ohm: 0.005; Value1: 0.005 ohm; VDC_V: 100; Value2: 100V; IRMS_A: 6.45; TaMin_C: -55; TaMax_C: 125; Cap_Case: 2220; SizeArea_mm2: 28.5; SizeAreaWB_mm2: 53.9; SizeX_mm: 5.7; SizeY_mm: 5; SizeZ_mm: 2.5; AEC Category: Q200
C40 = C2012X7R2A104K125AA: CAP, CERM, 0.1 µF, 100 V, +/- 10%, X7R, 0805; Manufacturer: TDK; Polarized: N; CompType: Capacitor; Value: 0.1uF; U/M: EA; Cap_F: 0.0000001; Tolerance_%: 10; ESR_ohm: 0.0158; Value1: 0.0158 ohm; VDC_V: 100; Value2: 100V; TaMin_C: -55; TaMax_C: 125; Cap_Case: 0805; AEC Category: Q200
C41 C44 = GRM188R72A104KA35D: CAP, CERM, 0.1 µF, 100 V, +/- 10%, X7R, 0603; Manufacturer: MuRata; Polarized: N; CompType: Capacitor; Value: 0.1uF; U/M: EA; Cap_F: 0.0000001; Tolerance_%: 10; Value1: Unknown; VDC_V: 100; Value2: 100V; TaMin_C: -55; TaMax_C: 125; Cap_Case: 0603; AEC Category: Q200
C42 = APXA160ARA181MHC0G: CAP, Aluminum Polymer, 180 µF, 16 V, +/- 20%, 0.016 ohm, HC0 SMD; Manufacturer: Chemi-Con; Polarized: Y; CompType: Capacitor; Value: 180uF; U/M: EA; Cap_F: 0.00018; Tolerance_%: 20; VDC_V: 16; Value2: 16V; ESR_ohm: 0.016; IRMS_A: 4.36; TaMin_C: -55; TaMax_C: 105; SizeAreaWB_mm2: 110.25; SizeArea_mm2: 72.25; SizeX_mm: 8.5; SizeZ_mm: 12.3; AEC Category: Q200; AEC Qualified: N
C43 = C2012X7R1C225K125AB: CAP, CERM, 2.2 µF, 16 V, +/- 10%, X7R, 0805; Manufacturer: TDK; Polarized: N; CompType: Capacitor; Value: 2.2uF; U/M: EA; Cap_F: 0.0000022; Tolerance_%: 10; ESR_ohm: 0.0049; Value1: 0.0049 ohm; VDC_V: 16; Value2: 16V; TaMin_C: -55; TaMax_C: 125; Cap_Case: 0805; AEC Category: Q200
C45 = C1608C0G2A331J080AA: CAP, CERM, 330 pF, 100 V, +/- 5%, C0G/NP0, 0603; Manufacturer: TDK; Polarized: N; CompType: Capacitor; Value: 330pF; U/M: EA; Cap_F: 0.00000000033; Tolerance_%: 5; ESR_ohm: 0.1269; Value1: 0.1269 ohm; VDC_V: 100; Value2: 100V; TaMin_C: -55; TaMax_C: 125; Cap_Case: 0603; AEC Category: Q200
C46 = GRM188R71H563KA93D: CAP, CERM, 0.056 µF, 50 V, +/- 10%, X7R, 0603; Manufacturer: MuRata; Polarized: N; CompType: Capacitor; Value: 0.056uF; U/M: EA; Cap_F: 0.000000056; Tolerance_%: 10; Value1: Unknown; VDC_V: 50; Value2: 50V; TaMin_C: -55; TaMax_C: 125; Cap_Case: 0603
C47 C48 = GRM188R71E105KA12D: as C11 on sheet SV601272A-Controller1
C49 = GRM1885C2A152JA01D: CAP, CERM, 1500 pF, 100 V, +/- 5%, C0G/NP0, 0603; Manufacturer: MuRata; Polarized: N; CompType: Capacitor; Value: 1500pF; U/M: EA; Cap_F: 0.0000000015; Tolerance_%: 5; Value1: Unknown; VDC_V: 100; Value2: 100V; TaMin_C: -55; TaMax_C: 125; Cap_Case: 0603
C76-C78 = CMP-0007891-2: CAP, CERM, 1 uF, 100 V, +/- 10%, X7S, 0805; PartNumber: C2012X7S2A105K125AB; Manufacturer: TDK; Polarized: N; Value: 1uF; U/M: EA; Cap_F: 1µF; ESR_ohm: 8.255m; Value1: 0.008255 ohm; VDC_V: 100V; IRMS_A: 2.27442A; TaMin_C: -55°C; TaMax_C: 125°C; Cap_Case: 0805; AEC Category: Q200; SizeArea_mm2: 2.5; SizeAreaWB_mm2: 6.75; SizeX_mm: 2; SizeY_mm: 1.25; SizeZ_mm: 1.45
C221 = GRM188R61A224KA01D: CAP, CERM, 0.22 µF, 10 V, +/- 10%, X5R, 0603; Manufacturer: MuRata; Polarized: N; CompType: Capacitor; Value: 0.22uF; U/M: EA; Cap_F: 0.00000022; Tolerance_%: 10; Value1: Unknown; Value2: 10V; TaMin_C: -55; TaMax_C: 85; SizeArea_mm2: 1.28; SizeAreaWB_mm2: 4.68; SizeX_mm: 1.6; SizeY_mm: 0.8; SizeZ_mm: 1; AEC Category: Q200
C222 = GRM188R61A475MAAJ: CAP, CERM, 4.7 µF, 10 V, +/- 20%, X5R, 0603; Manufacturer: MuRata; Polarized: N; CompType: Capacitor; Value: 4.7uF; U/M: EA; Cap_F: 0.0000047; Tolerance_%: 20; Value1: Unknown; VDC_V: 10; Value2: 10V; TaMin_C: -55; TaMax_C: 85; SizeArea_mm2: 1.28; SizeAreaWB_mm2: 4.68; SizeX_mm: 1.6; SizeY_mm: 0.8; SizeZ_mm: 1; AEC Category: Q200
C223 C228 C229 = GRM188R61A106ME69D: CAP, CERM, 10 µF, 10 V, +/- 20%, X5R, 0603; Manufacturer: MuRata; Polarized: N; CompType: Capacitor; Value: 10uF; U/M: EA; Cap_F: 0.00001; Tolerance_%: 20; Value1: Unknown; VDC_V: 10; Value2: 10V; TaMin_C: -55; TaMax_C: 85; SizeArea_mm2: 1.28; SizeAreaWB_mm2: 4.68; SizeX_mm: 1.6; SizeY_mm: 0.8; SizeZ_mm: 1; AEC Category: Q200
C224 C226 = GRM188R60J226MEA0D: CAP, CERM, 22 µF, 6.3 V, +/- 20%, X5R, 0603; Manufacturer: MuRata; Polarized: N; CompType: Capacitor; Value: 22uF; U/M: EA; Cap_F: 0.000022; Tolerance_%: 20; Value1: Unknown; VDC_V: 6.3; Value2: 6.3V; TaMin_C: -55; TaMax_C: 85; SizeArea_mm2: 1.28; SizeAreaWB_mm2: 4.68; SizeX_mm: 1.6; SizeY_mm: 0.8; SizeZ_mm: 1; AEC Category: Q200
C225 = GRM188R61C104KA01D: CAP, CERM, 0.1 µF, 16 V, +/- 10%, X5R, 0603; Manufacturer: MuRata; Polarized: N; CompType: Capacitor; Value: 0.1uF; U/M: EA; Cap_F: 0.0000001; Tolerance_%: 10; Value1: Unknown; VDC_V: 16; Value2: 16V; TaMin_C: -55; TaMax_C: 85; SizeArea_mm2: 1.28; SizeAreaWB_mm2: 4.68; SizeX_mm: 1.6; SizeY_mm: 0.8; SizeZ_mm: 1; AEC Category: Q200
C227 = GRM188R71E474KA12D: CAP, CERM, 0.47 µF, 25 V, +/- 10%, X7R, 0603; Manufacturer: MuRata; Polarized: N; CompType: Capacitor; Value: 0.47uF; U/M: EA; Cap_F: 0.00000047; Tolerance_%: 10; Value1: Unknown; VDC_V: 25; Value2: 25V; TaMin_C: -55; TaMax_C: 125; SizeArea_mm2: 1.28; SizeAreaWB_mm2: 4.68; SizeX_mm: 1.6; SizeY_mm: 0.8; SizeZ_mm: 1; AEC Category: Q200
D6 = B530C-13-F: Diode, Schottky, 30 V, 5 A, SMC; Manufacturer: Diodes Inc.; U/M: EA; Vf_V: 0.55; Value: 30V; Value1: 5A; Value2: 0.55V; Io_A: 5; Vr_V: 30; TJmax_C: 125; RJC_CperW: 10
D7 = CDBC5100-G: Diode, Schottky, 100 V, 5 A, SMC; Manufacturer: Comchip Technology; U/M: EA; Vf_V: 0.85; Value: 100V; Value1: 5A; Value2: 0.85V; Io_A: 5; Vr_V: 100; TJmax_C: 125
J4 J16 = HTSW-102-07-G-S: as J3 on sheet SV601272A-Controller1
J23 = HTSW-103-07-G-S: as J1 on sheet SV601272A-Controller1
L3 = MSS1278-473MLB: Inductor, Shielded Drum Core, Ferrite, 47 µH, 2.9 A, 0.07 ohm, SMD; Manufacturer: Coilcraft; Value: 47uH; Ind_H: 47.0E-6; ValueDisplayed: 47µH; Imax_A: 2.9; Irms: 2.9A @ 40C rise; Isat: 5.32A @ 30% inductance drop; DCR_ohm: 0.07; Value2: 2.9A
L7 L8 = MPZ2012S601A: Ferrite Bead, 600 ohm @ 100MHz, 2A, 0805; Manufacturer: TDK; Imax_A: 2; DCR_ohm: 0.1; Value1: 0.1 ohm; ZTyp@100MHz_Ohm: 600
NT2 = Net-Tie: as NT1 on sheet SV601272A-Controller1
Q14 Q15 = SI7454DDP-T1-GE3: MOSFET, N-CH, 100 V, 21 A, PowerPAK SO-8; Manufacturer: Vishay-Siliconix; Alternate Manufacturer: None; U/M: EA; ChType: N; Value: 100V; VdsMax_V: 100; Value1: 0.047 ohm; Rdson45_ohm: 0.047; Value2: 12.8 nC; QgTyp_nC: 12.8; Vgs_V: 20; IdsMax_A: 21; SizeAreaWB_mm2: 55.131; SizeArea_mm2: 29.351; SizeX_mm: 5.99; SizeY_mm: 4.9; SizeZ_mm: 1.12; AEC Category: Q101
R10 = CMP-0022680-4: RES, 1.00 k, 1%, 0.1 W, 0603; Manufacturer: Panasonic; Power_W: 100mW; TempCo: 100 ppm/C; Value_Code: 1k00; U/M: EA; Value: 1.00k; EIA_Code: E96; Res_ohm: 1k; SizeX_mm: 1.6; SizeY_mm: 0.8; SizeZ_mm: 1; SizeArea_mm2: 1.28; CompType: Resistor; VDC_V: 75V; AEC Category: Q200; Value2: 0.1W
R46 = CRCW060318K2FKEA: RES, 18.2 k, 1%, 0.1 W, 0603; Manufacturer: Vishay-Dale; CompType: Resistor; Value: 18.2k; Res_ohm: 18200; Value_Code: 18k2; Tolerance_%: 1; Power_W: 0.1; Value2: 0.1W; VDC_V: 75; TempCo: 100 ppm/C; EIA_Code: E96; U/M: EA
R47 = PRL1632-R068-F-T1: RES, 0.068, 1%, 1 W, 0612; Manufacturer: Susumu Co Ltd; CompType: Resistor; Value: 0.068; Value_Code: R068; Tolerance_%: 1; Value2: 1W; TempCo: 50 ppm/C; U/M: EA
R48 = RC0603FR-0724KL: RES, 24.0 k, 1%, 0.1 W, 0603; Manufacturer: Yageo America; CompType: Resistor; Value: 24.0k; Res_ohm: 24000; Value_Code: 24k0; Tolerance_%: 1; Power_W: 0.1; Value2: 0.1W; VDC_V: 150; TempCo: 200 ppm/C; U/M: EA
R49 = CMP-0023278-3: RES, 7.32 k, 1%, 0.1 W, 0603; Manufacturer: Yageo America; Power_W: 100mW; TempCo: 200 ppm/C; Value_Code: 7k32; U/M: EA; Value: 7.32k; EIA_Code: E96; SizeX_mm: 1.6; SizeY_mm: 0.8; SizeZ_mm: 1; Value2: 0.1W; SizeArea_mm2: 1.28; CompType: Resistor; VDC_V: 150V; AEC Category: Q200
R50 = CMP-0023172-3: RES, 52.3 k, 1%, 0.1 W, 0603; Manufacturer: Yageo America; Power_W: 100mW; TempCo: 200 ppm/C; Value_Code: 52k3; U/M: EA; Value: 52.3k; EIA_Code: E96; SizeX_mm: 1.6; SizeY_mm: 0.8; SizeZ_mm: 1; Value2: 0.1W; SizeArea_mm2: 1.28; CompType: Resistor; VDC_V: 150V; AEC Category: Q200
R51 = CRCW060310R0FKEA: RES, 10.0, 1%, 0.1 W, 0603; Manufacturer: Vishay-Dale; CompType: Resistor; Value: 10.0; Res_ohm: 10; Value_Code: 10R0; Tolerance_%: 1; Power_W: 0.1; Value2: 0.1W; VDC_V: 75; TempCo: 100 ppm/C; EIA_Code: E96; U/M: EA
R53 = CRCW060320K0FKEA: RES, 20.0 k, 1%, 0.1 W, 0603; Manufacturer: Vishay-Dale; CompType: Resistor; Value: 20.0k; Res_ohm: 20000; Value_Code: 20k0; Tolerance_%: 1; Power_W: 0.1; Value2: 0.1W; VDC_V: 75; TempCo: 100 ppm/C; EIA_Code: E96; U/M: EA; AEC Category: Q200
R164 R165 = CMP-0025874-3: as R160 on sheet SV601272A-Controller1
R201 = RT0603DRE074R7L: RES, 4.70, 0.5%, 0.1 W, 0603; Manufacturer: Yageo America; CompType: Resistor; Value: 4.70; Res_ohm: 4.7; Value_Code: 4R70; Tolerance_%: 0.5; Power_W: 0.1; Value2: 0.1W; VDC_V: 75; TempCo: 50 ppm/C; SizeArea_mm2: 1.28; SizeX_mm: 1.6; SizeY_mm: 0.8; SizeZ_mm: 1; EIA_Code: E192; U/M: EA; AEC Category: Q200
U3 U4 = TPS70950DBVR: 150-mA, 30-V, 1-uA IQ Voltage Regulators with Enable, DBV0005A; Alternate PartNumber: TPS70950DBVT; Manufacturer: Texas Instruments; SymbolCreator: Altium; CompType: IC; U/M: EA
U5 = LM5118MH/NOPB: Wide Voltage Range Buck-Boost Controller, 20-pin TSSOP-EP, Pb-Free; Manufacturer: Texas Instruments; PackageTopMarking: NSUZXYTT*LM5118*MH; PowerWise: Y; CompType: Switcher
U7 = CMP-0072146-1: Switched Capacitor Voltage Converter, 6-pin SOT-23; Manufacturer: Texas Instruments; PackageTopMarking: S03A*XTT; PowerWise: N; CompType: Switch Caps
U29 = LM7705MM/NOPB: Low Noise Negative Bias Generator, 8-pin Mini SOIC, Pb-Free; Manufacturer: Texas Instruments; PackageTopMarking: ZXTT*F26A; PowerWise: N; CompType: OtherParts
V-5 = PogoPad: Pad for Pogo Pin Connector; SymbolCreator: codlsc

## Sheet SV601272A-Power.SchDoc: Power Stage
size 431 x 279 mm; Date: Not shown in title block; ApprovedBy: Not shown in title block; CheckedBy: Not shown in title block; Author: Not shown in title block; CompanyName: Not shown in title block; Engineer: Not shown in title block; Organization: Not shown in title block; Address1: Not shown in title block; Address2: Not shown in title block; Address3: Not shown in title block; Address4: Not shown in title block; DocumentNumber: 5; Revision: Use project parameter SCH_Rev; SheetNumber: 5; SheetTotal: 11; PageSetup: Record=PageOptions¦CenterHorizontal=True¦CenterVertical=True¦PrintScale=0.62¦XCorrection=1.00¦YCorrection=1.00¦PrintKind=0¦BorderSize=5000000¦LeftOffset=0¦BottomOffset=0¦Orientation=2¦PaperLength=1000¦PaperWidth=1000¦Scale=100¦PaperSource=15¦PrintQuality=600¦MediaType=1¦DitherType=10¦PrintScaleMode=1¦PaperKind=Letter (8.5 x 11")¦PaperIndex=1
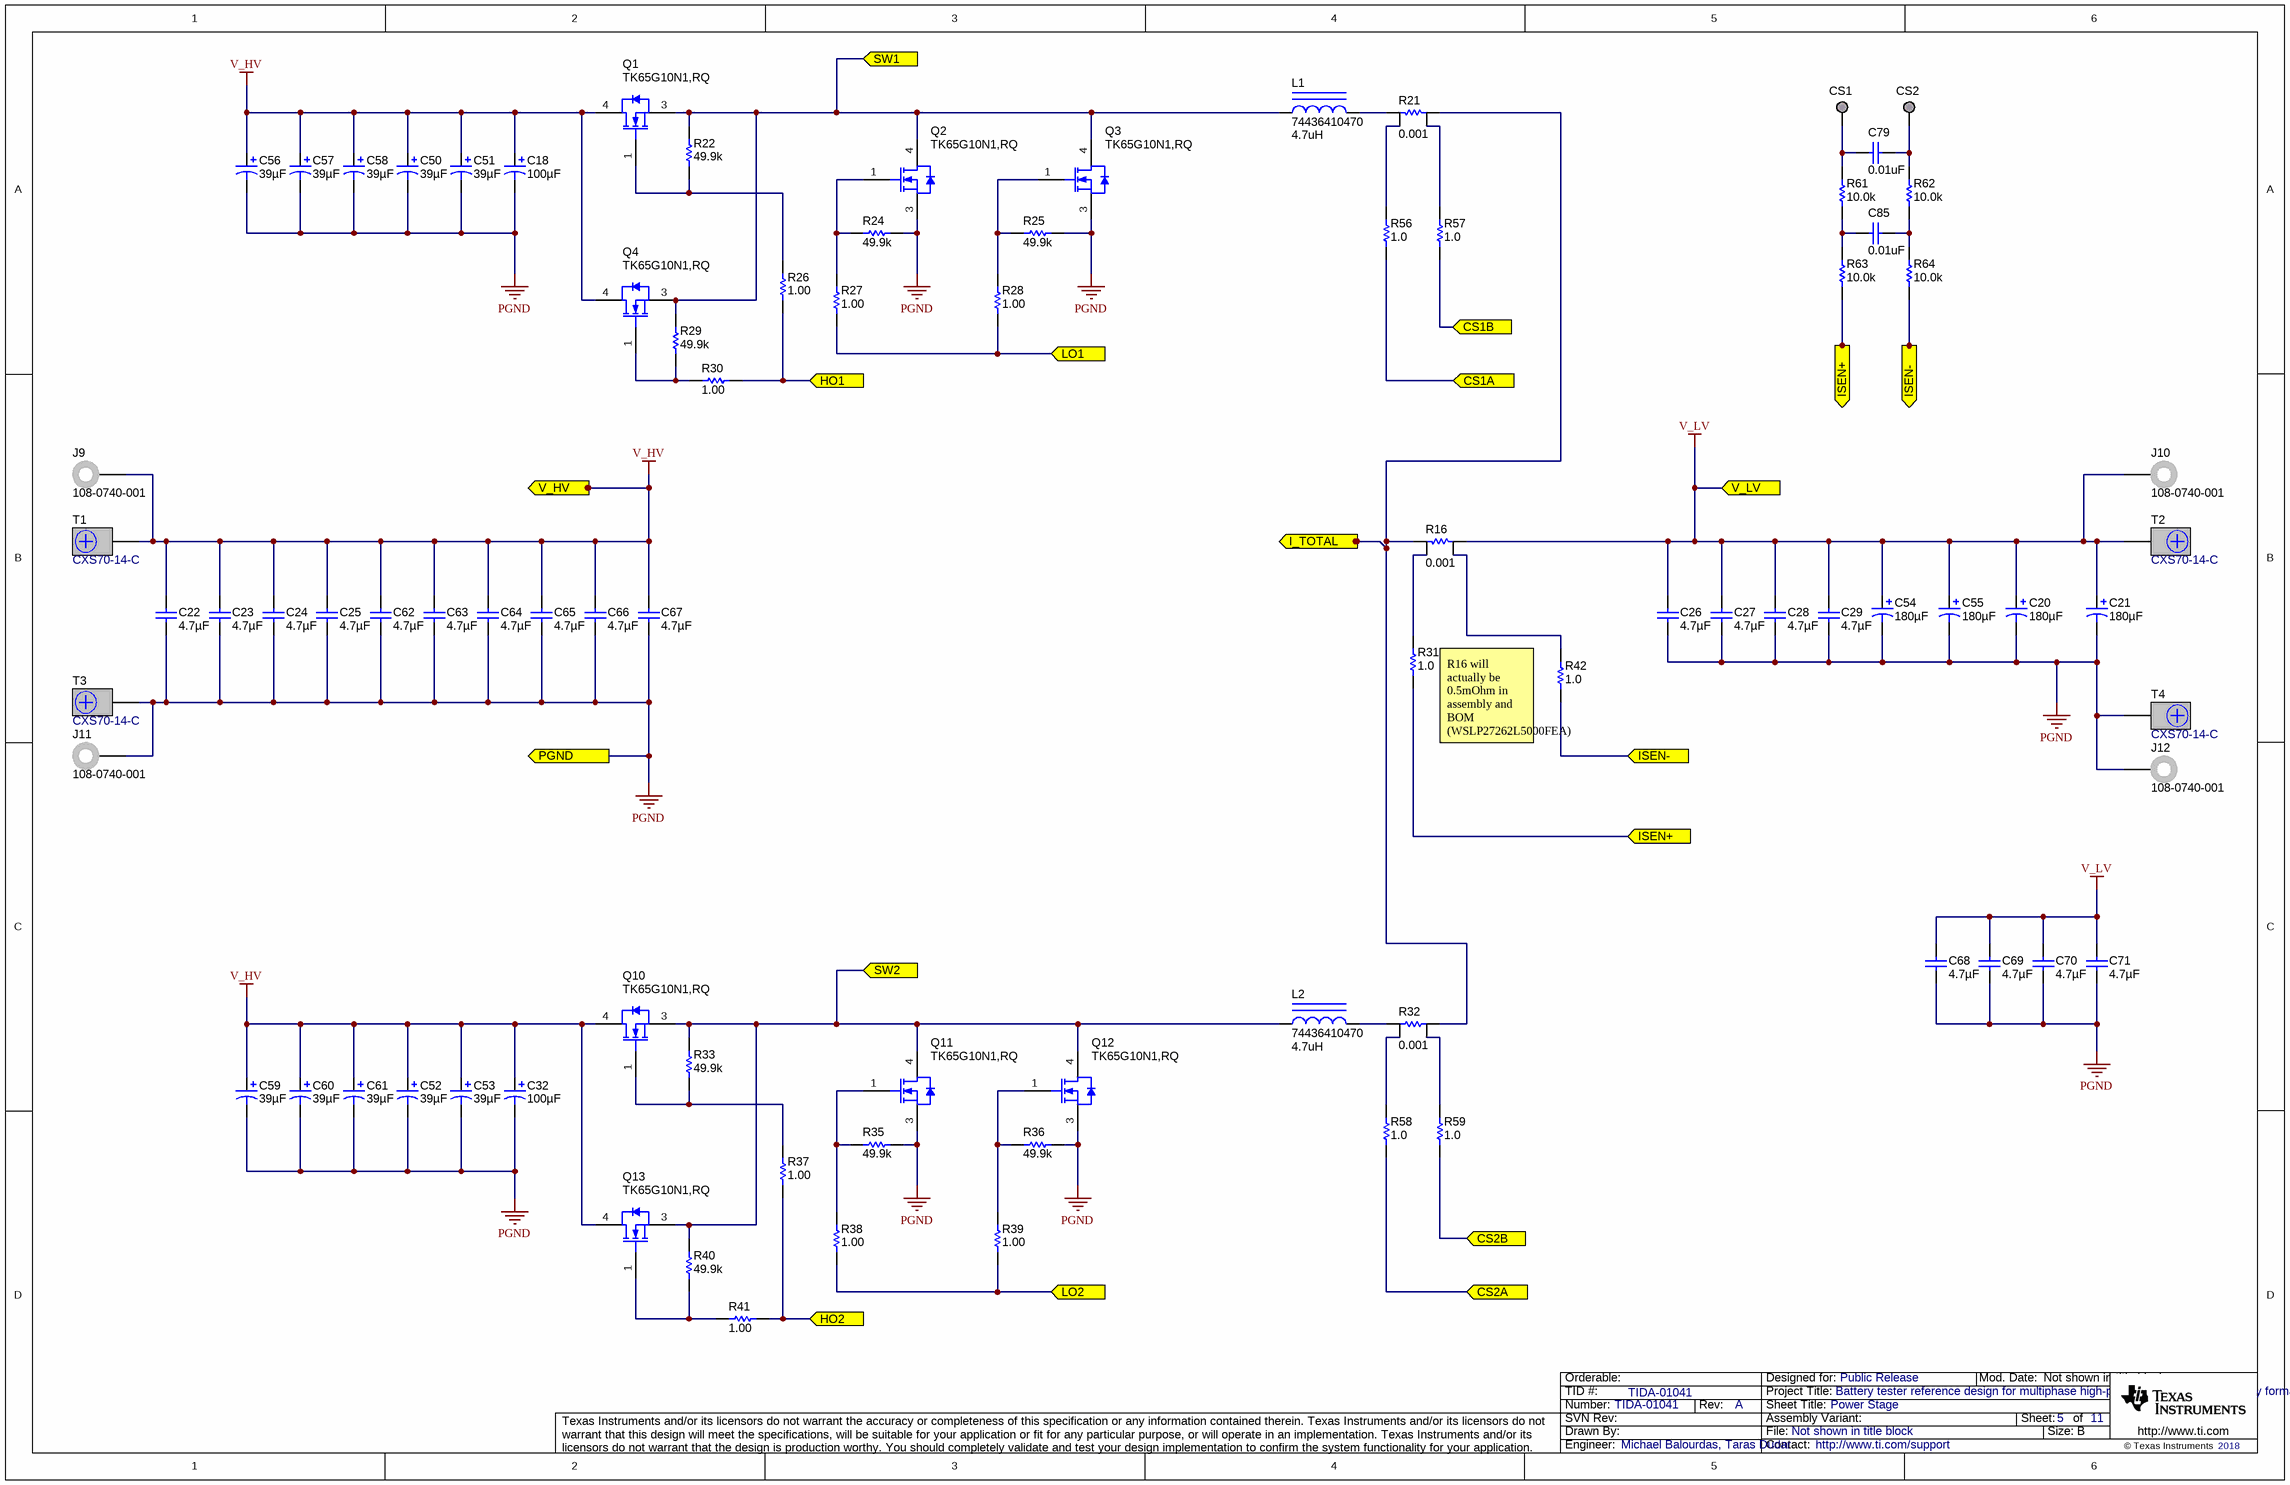
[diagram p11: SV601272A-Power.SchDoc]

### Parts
C18  ValueDisplayed: 100µF  [CAPSMT_62_LH0]  (hidden comment: EMVH101GDA101MLH0S)
C20  ValueDisplayed: 180µF  [CR_1000x1270]  (hidden comment: PCR1H181MCL1GS)
C21  ValueDisplayed: 180µF  [CR_1000x1270]  (hidden comment: PCR1H181MCL1GS)
C22  ValueDisplayed: 4.7µF  [2220_280]  (hidden comment: C5750X7R2A475M230KA)
C23  ValueDisplayed: 4.7µF  [2220_280]  (hidden comment: C5750X7R2A475M230KA)
C24  ValueDisplayed: 4.7µF  [2220_280]  (hidden comment: C5750X7R2A475M230KA)
C25  ValueDisplayed: 4.7µF  [2220_280]  (hidden comment: C5750X7R2A475M230KA)
C26  ValueDisplayed: 4.7µF  [2220_280]  (hidden comment: C5750X7R2A475M230KA)
C27  ValueDisplayed: 4.7µF  [2220_280]  (hidden comment: C5750X7R2A475M230KA)
C28  ValueDisplayed: 4.7µF  [2220_280]  (hidden comment: C5750X7R2A475M230KA)
C29  ValueDisplayed: 4.7µF  [2220_280]  (hidden comment: C5750X7R2A475M230KA)
C32  ValueDisplayed: 100µF  [CAPSMT_62_LH0]  (hidden comment: EMVH101GDA101MLH0S)
C50  ValueDisplayed: 39µF  [HXA_JA0]  (hidden comment: HHXA800ARA390MJA0G)
C51  ValueDisplayed: 39µF  [HXA_JA0]  (hidden comment: HHXA800ARA390MJA0G)
C52  ValueDisplayed: 39µF  [HXA_JA0]  (hidden comment: HHXA800ARA390MJA0G)
C53  ValueDisplayed: 39µF  [HXA_JA0]  (hidden comment: HHXA800ARA390MJA0G)
C54  ValueDisplayed: 180µF  [CR_1000x1270]  (hidden comment: PCR1H181MCL1GS)
C55  ValueDisplayed: 180µF  [CR_1000x1270]  (hidden comment: PCR1H181MCL1GS)
C56  ValueDisplayed: 39µF  [HXA_JA0]  (hidden comment: HHXA800ARA390MJA0G)
C57  ValueDisplayed: 39µF  [HXA_JA0]  (hidden comment: HHXA800ARA390MJA0G)
C58  ValueDisplayed: 39µF  [HXA_JA0]  (hidden comment: HHXA800ARA390MJA0G)
C59  ValueDisplayed: 39µF  [HXA_JA0]  (hidden comment: HHXA800ARA390MJA0G)
C60  ValueDisplayed: 39µF  [HXA_JA0]  (hidden comment: HHXA800ARA390MJA0G)
C61  ValueDisplayed: 39µF  [HXA_JA0]  (hidden comment: HHXA800ARA390MJA0G)
C62  ValueDisplayed: 4.7µF  [2220_280]  (hidden comment: C5750X7R2A475M230KA)
C63  ValueDisplayed: 4.7µF  [2220_280]  (hidden comment: C5750X7R2A475M230KA)
C64  ValueDisplayed: 4.7µF  [2220_280]  (hidden comment: C5750X7R2A475M230KA)
C65  ValueDisplayed: 4.7µF  [2220_280]  (hidden comment: C5750X7R2A475M230KA)
C66  ValueDisplayed: 4.7µF  [2220_280]  (hidden comment: C5750X7R2A475M230KA)
C67  ValueDisplayed: 4.7µF  [2220_280]  (hidden comment: C5750X7R2A475M230KA)
C68  ValueDisplayed: 4.7µF  [2220_280]  (hidden comment: C5750X7R2A475M230KA)
C69  ValueDisplayed: 4.7µF  [2220_280]  (hidden comment: C5750X7R2A475M230KA)
C70  ValueDisplayed: 4.7µF  [2220_280]  (hidden comment: C5750X7R2A475M230KA)
C71  ValueDisplayed: 4.7µF  [2220_280]  (hidden comment: C5750X7R2A475M230KA)
C79  ValueDisplayed: 0.01uF  [0603L]  (hidden comment: Capacitor)
C85  ValueDisplayed: 0.01uF  [0603L]  (hidden comment: Capacitor)
CS1  TESTPOINT  [TP_25MIL-SMT]  (value not drawn)  (no BOM)
CS2  TESTPOINT  [TP_25MIL-SMT]  (value not drawn)  (no BOM)
J9  108-0740-001  [Johnson_108-0740-001]
J10  108-0740-001  [Johnson_108-0740-001]
J11  108-0740-001  [Johnson_108-0740-001]
J12  108-0740-001  [Johnson_108-0740-001]
L1  74436410470  value 4.7uH  [WE-HCF_2818]
L2  74436410470  value 4.7uH  [WE-HCF_2818]
Q1  TK65G10N1,RQ  [DDPAK]
Q2  TK65G10N1,RQ  [DDPAK]
Q3  TK65G10N1,RQ  [DDPAK]
Q4  TK65G10N1,RQ  [DDPAK]
Q10  TK65G10N1,RQ  [DDPAK]
Q11  TK65G10N1,RQ  [DDPAK]
Q12  TK65G10N1,RQ  [DDPAK]
Q13  TK65G10N1,RQ  [DDPAK]
R16  ValueDisplayed: 0.001  [RES_WSL2726]  (hidden comment: WSLP27261L000FEA)
R21  ValueDisplayed: 0.001  [RES_WSL2726]  (hidden comment: WSL27261L000FEB)
R22  ValueDisplayed: 49.9k  [0805_HV]  (hidden comment: CRCW080549K9FKEA)
R24  ValueDisplayed: 49.9k  [0805_HV]  (hidden comment: CRCW080549K9FKEA)
R25  ValueDisplayed: 49.9k  [0805_HV]  (hidden comment: CRCW080549K9FKEA)
R26  ValueDisplayed: 1.00  [0805_HV]  (hidden comment: CRCW08051R00FKEA)
R27  ValueDisplayed: 1.00  [0805_HV]  (hidden comment: CRCW08051R00FKEA)
R28  ValueDisplayed: 1.00  [0805_HV]  (hidden comment: CRCW08051R00FKEA)
R29  ValueDisplayed: 49.9k  [0805_HV]  (hidden comment: CRCW080549K9FKEA)
R30  ValueDisplayed: 1.00  [0805_HV]  (hidden comment: CRCW08051R00FKEA)
R31  ValueDisplayed: 1.0  [0603L]  (hidden comment: CRCW06031R00JNEA)
R32  ValueDisplayed: 0.001  [RES_WSL2726]  (hidden comment: WSL27261L000FEB)
R33  ValueDisplayed: 49.9k  [0805_HV]  (hidden comment: CRCW080549K9FKEA)
R35  ValueDisplayed: 49.9k  [0805_HV]  (hidden comment: CRCW080549K9FKEA)
R36  ValueDisplayed: 49.9k  [0805_HV]  (hidden comment: CRCW080549K9FKEA)
R37  ValueDisplayed: 1.00  [0805_HV]  (hidden comment: CRCW08051R00FKEA)
R38  ValueDisplayed: 1.00  [0805_HV]  (hidden comment: CRCW08051R00FKEA)
R39  ValueDisplayed: 1.00  [0805_HV]  (hidden comment: CRCW08051R00FKEA)
R40  ValueDisplayed: 49.9k  [0805_HV]  (hidden comment: CRCW080549K9FKEA)
R41  ValueDisplayed: 1.00  [0805_HV]  (hidden comment: CRCW08051R00FKEA)
R42  ValueDisplayed: 1.0  [0603L]  (hidden comment: CRCW06031R00JNEA)
R56  ValueDisplayed: 1.0  [0603L]  (hidden comment: CRCW06031R00JNEA)
R57  ValueDisplayed: 1.0  [0603L]  (hidden comment: CRCW06031R00JNEA)
R58  ValueDisplayed: 1.0  [0603L]  (hidden comment: CRCW06031R00JNEA)
R59  ValueDisplayed: 1.0  [0603L]  (hidden comment: CRCW06031R00JNEA)
R61  ValueDisplayed: 10.0k  [0603L]  (hidden comment: Resistor)
R62  ValueDisplayed: 10.0k  [0603L]  (hidden comment: Resistor)
R63  ValueDisplayed: 10.0k  [0603L]  (hidden comment: Resistor)
R64  ValueDisplayed: 10.0k  [0603L]  (hidden comment: Resistor)
T1  CXS70-14-C  [Panduit_CXS70-14-C]
T2  CXS70-14-C  [Panduit_CXS70-14-C]
T3  CXS70-14-C  [Panduit_CXS70-14-C]
T4  CXS70-14-C  [Panduit_CXS70-14-C]

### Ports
CS1A, CS1B, CS2A, CS2B, HO1, HO2, I_TOTAL, ISEN+, ISEN-, LO1, LO2, PGND, SW1, SW2, V_HV, V_LV

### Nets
PGND: C18.2(-) C20.2(-) C21.2(-) C22.2 C23.2 C24.2 C25.2 C26.2 C27.2 C28.2 C29.2 C32.2(-) C50.2(-) C51.2(-) C52.2(-) C53.2(-) C54.2(-) C55.2(-) C56.2(-) C57.2(-) C58.2(-) C59.2(-) C60.2(-) C61.2(-) C62.2 C63.2 C64.2 C65.2 C66.2 C67.2 C68.2 C69.2 C70.2 C71.2 J11.1 J12.1 Q2.3(S) Q3.3(S) Q11.3(S) Q12.3(S) R24.2 R25.2 R35.2 R36.2 T3.1 T4.1 ; port PGND
V_HV: C18.1(+) C22.1 C23.1 C24.1 C25.1 C32.1(+) C50.1(+) C51.1(+) C52.1(+) C53.1(+) C56.1(+) C57.1(+) C58.1(+) C59.1(+) C60.1(+) C61.1(+) C62.1 C63.1 C64.1 C65.1 C66.1 C67.1 J9.1 Q1.4(D) Q4.4(D) Q10.4(D) Q13.4(D) T1.1 ; port V_HV
V_LV: C20.1(+) C21.1(+) C26.1 C27.1 C28.1 C29.1 C54.1(+) C55.1(+) C68.1 C69.1 C70.1 C71.1 J10.1 R16.2 T2.1 ; port V_LV
CS1A: R56.1 ; port CS1A
CS1B: R57.1 ; port CS1B
CS2A: R58.1 ; port CS2A
CS2B: R59.1 ; port CS2B
HO1: R26.1 R30.1 ; port HO1
HO2: R37.1 R41.1 ; port HO2
I_TOTAL: R16.1 R21.2 R32.1 ; port I_TOTAL
ISEN+: R31.1 R63.1 ; port ISEN+
ISEN-: R42.1 R64.1 ; port ISEN-
LO1: R27.1 R28.1 ; port LO1
LO2: R38.1 R39.1 ; port LO2
SW1: L1.1 Q1.3(S) Q2.4(D) Q3.4(D) Q4.3(S) R22.1 R29.1 ; port SW1
SW2: L2.2 Q10.3(S) Q11.4(D) Q12.4(D) Q13.3(S) R33.2 R40.2 ; port SW2
NetC79_1: C79.1 CS2.1 R62.2
NetC79_2: C79.2 CS1.1 R61.2
NetC85_1: C85.1 R62.1 R64.2
NetC85_2: C85.2 R61.1 R63.2
NetL1_2: L1.2 R21.1
NetL2_1: L2.1 R32.2
NetQ1_1: Q1.1(G) R22.2 R26.2
NetQ2_1: Q2.1(G) R24.1 R27.2
NetQ3_1: Q3.1(G) R25.1 R28.2
NetQ4_1: Q4.1(G) R29.2 R30.2
NetQ10_1: Q10.1(G) R33.1 R37.2
NetQ11_1: Q11.1(G) R35.1 R38.2
NetQ12_1: Q12.1(G) R36.1 R39.2
NetQ13_1: Q13.1(G) R40.1 R41.2
NetR16_3: R16.3 R31.2
NetR16_4: R16.4 R42.2
NetR21_3: R21.3 R56.2
NetR21_4: R21.4 R57.2
NetR32_3: R32.3 R59.2
NetR32_4: R32.4 R58.2

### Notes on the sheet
- R16 will actually be 0.5mOhm in assembly and BOM (WSLP27262L5000FEA)

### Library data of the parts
C18 C32 = EMVH101GDA101MLH0S: CAP, AL, 100 µF, 100 V, +/- 20%, 0.24 ohm, SMD; Manufacturer: Chemi-Con; Polarized: Y; CompType: Capacitor; Value: 100uF; U/M: EA; Cap_F: 0.0001; Tolerance_%: 20; VDC_V: 100; Value2: 100V; ESR_ohm: 0.24; IRMS_A: 0.65; TaMin_C: -40; TaMax_C: 125; Cap_Case: LH0
C20 C21 C54 C55 = PCR1H181MCL1GS: CAP, AL, 180 µF, 50 V, +/- 20%, 0.019 ohm, SMD; Manufacturer: Nichicon; Polarized: Y; CompType: Capacitor; Value: 180uF; U/M: EA; Cap_F: 0.00018; Tolerance_%: 20; VDC_V: 50; Value2: 50V; ESR_ohm: 0.019; IRMS_A: 3.5; TaMin_C: -55; TaMax_C: 125; Cap_Case: 10x12.7mm
C22-C29 C62-C71 = C5750X7R2A475M230KA: CAP, CERM, 4.7 µF, 100 V, +/- 20%, X7R, 2220; Manufacturer: TDK; Polarized: N; CompType: Capacitor; Value: 4.7uF; U/M: EA; Cap_F: 0.0000047; Tolerance_%: 20; ESR_ohm: 0.0015; Value1: 0.0015 ohm; VDC_V: 100; Value2: 100V; IRMS_A: 5.5; TaMin_C: -55; TaMax_C: 125; Cap_Case: 2220; AEC Category: Q200
C50-C53 C56-C61 = HHXA800ARA390MJA0G: CAP, Aluminum Polymer, 39 µF, 80 V, +/- 20%, 0.035 ohm, AEC-Q200 Grade 1, D10xL10mm SMD; Manufacturer: Chemi-Con; CompType: Capacitor; U/M: EA; ESR_ohm: 0.035; VDC_V: 80; Tolerance_%: 20; Value: 39uF; Polarized: Y; Cap_F: 0.000039; Value2: 80V; IRMS_A: 1.2; TaMin_C: -55; TaMax_C: 125; Cap_Case: 10X10mm; AEC Category: Q200; AEC Grade: 1
C79 C85 = CMP-0006727-4: CAP, CERM, 0.01 uF, 100 V, +/- 10%, X7R, 0603; PartNumber: 06031C103KAT2A; Manufacturer: AVX; Polarized: N; Value: 0.01uF; U/M: EA; Cap_F: 10nF; ESR_ohm: 0.098; Value1: 0.098 ohm; VDC_V: 100V; TaMin_C: -55°C; TaMax_C: 125°C; Cap_Case: 0603; AEC Category: Q200; SizeArea_mm2: 1.28; SizeAreaWB_mm2: 4.68; SizeX_mm: 1.6; SizeY_mm: 0.8; SizeZ_mm: 1
CS1 CS2 = CMP-0078143-2: TEST POINT.  No entry in BOM.
J9-J12 = 108-0740-001: Standard Banana Jack, Uninsulated, 15A; Manufacturer: Emerson Network Power; SymbolCreator: a0412235; CompType: Connector; U/M: EA
L1 L2 = 744364410470: Inductor, 4.7uH, SMT; Manufacturer: WURTH; SymbolCreator: a0413446; U/M: EA
Q1-Q4 Q10-Q13 = TK65G10N1,RQ: MOSFET N CH 100V D2PAK; Manufacturer: Toshiba Semiconductor and Storage; SymbolVersion: use current date i.e. 2008-05-20; CompType: Used in some BOM reports.  Useful for finding later.; U/M: EA, IN, or GM; SymbolCreator: Use a-id; Power - Max: 156W; Current - Continuous Drain (Id) @ 25°C: 65A (Ta); FET Type: MOSFET N-Channel, Metal Oxide; FET Feature: Standard; Vgs(th) (Max) @ Id: 4V @ 1mA; Input Capacitance (Ciss) @ Vds: 5400pF @ 50V; Rds On (Max) @ Id, Vgs: 4.5 mOhm @ 32.5A, 10V; Gate Charge (Qg) @ Vgs: 81nC @ 10V
R16 = CMP-0080414-1: RES, 0.001, 1%, 7 W, AEC-Q200 Grade 0, 6.6x3x6.9mm; Manufacturer: Vishay-Dale; Value_Code: 1L000; AEC Qualified: Y; AEC Category: Q200; Res_ohm: 1m; Value: 0.001; EIA_Code: E96; TempCo: 75 ppm/C; AEC Grade: 0; Power_W: 7W; CompType: Resistor
R21 R32 = WSL27261L000FEB: RES, 0.001, 1%, 3 W, 6.6x3x6.9mm; Manufacturer: Vishay-Dale; CompType: Resistor; U/M: EA; Tolerance_%: 1; Value: 0.001; TempCo: 75 ppm/C; Power_W: 3; Value_Code: 1L000; Value2: 3W; EIA_Code: E96; AEC Category: Q200
R22 R24 R25 R29 R33 R35 R36 R40 = CRCW080549K9FKEA: RES, 49.9 k, 1%, 0.125 W, 0805; Manufacturer: Vishay-Dale; CompType: Resistor; Value: 49.9k; Res_ohm: 49900; Value_Code: 49k9; Tolerance_%: 1; Power_W: 0.125; Value2: 0.125W; VDC_V: 150; TempCo: 100 ppm/C; EIA_Code: E96; U/M: EA
R26-R28 R30 R37-R39 R41 = CRCW08051R00FKEA: RES, 1.00, 1%, 0.125 W, 0805; Manufacturer: Vishay-Dale; CompType: Resistor; Value: 1.00; Res_ohm: 1; Value_Code: 1R00; Power_W: 0.125; Value2: 0.125W; VDC_V: 150; TempCo: 100 ppm/C; EIA_Code: E96; U/M: EA
R31 R42 R56-R59 = CRCW06031R00JNEA: RES, 1.0, 5%, 0.1 W, 0603; Manufacturer: Vishay-Dale; CompType: Resistor; Value: 1.0; Res_ohm: 1; Value_Code: 1R00; Tolerance_%: 5; Power_W: 0.1; Value2: 0.1W; VDC_V: 75; TempCo: 200 ppm/C; EIA_Code: E24; U/M: EA; AEC Category: Q200
R61-R64 = CMP-0021998-4: RES, 10.0 k, 1%, 0.1 W, AEC-Q200 Grade 0, 0603; PartNumber: CRCW060310K0FKEA; Manufacturer: Vishay-Dale; Value: 10.0k; Res_ohm: 10k; Value_Code: 10k0; Power_W: 100mW; Value2: 0.1W; VDC_V: 75V; TempCo: 100 ppm/C; EIA_Code: E96; AEC Category: Q200; AEC Qualified: Y; AEC Grade: 0; SizeArea_mm2: 1.28; SizeX_mm: 1.6; SizeY_mm: 0.8; SizeZ_mm: 1
T1-T4 = CXS70-14-C: Terminal 70A Lug; Manufacturer: Panduit; SymbolCreator: crossc; CompType: Screw Terminal; U/M: EA

## Sheet SV601272A-Current-Control REV3.SchDoc
size 431 x 279 mm; Date: Not shown in title block; ApprovedBy: Not shown in title block; CheckedBy: Not shown in title block; Author: Not shown in title block; CompanyName: Not shown in title block; Engineer: Not shown in title block; Organization: Not shown in title block; Address1: Not shown in title block; Address2: Not shown in title block; Address3: Not shown in title block; Address4: Not shown in title block; DocumentNumber: 6; Revision: Use project parameter SCH_Rev; SheetNumber: 6; SheetTotal: 11; PageSetup: Record=PageOptions¦CenterHorizontal=True¦CenterVertical=True¦PrintScale=1.00¦XCorrection=1.00¦YCorrection=1.00¦PrintKind=0¦BorderSize=5000000¦LeftOffset=0¦BottomOffset=0¦Orientation=2¦PaperLength=1000¦PaperWidth=1000¦Scale=100¦PaperSource=15¦PrintQuality=600¦MediaType=1¦DitherType=10¦PaperKind=Letter¦PrintScaleMode=1
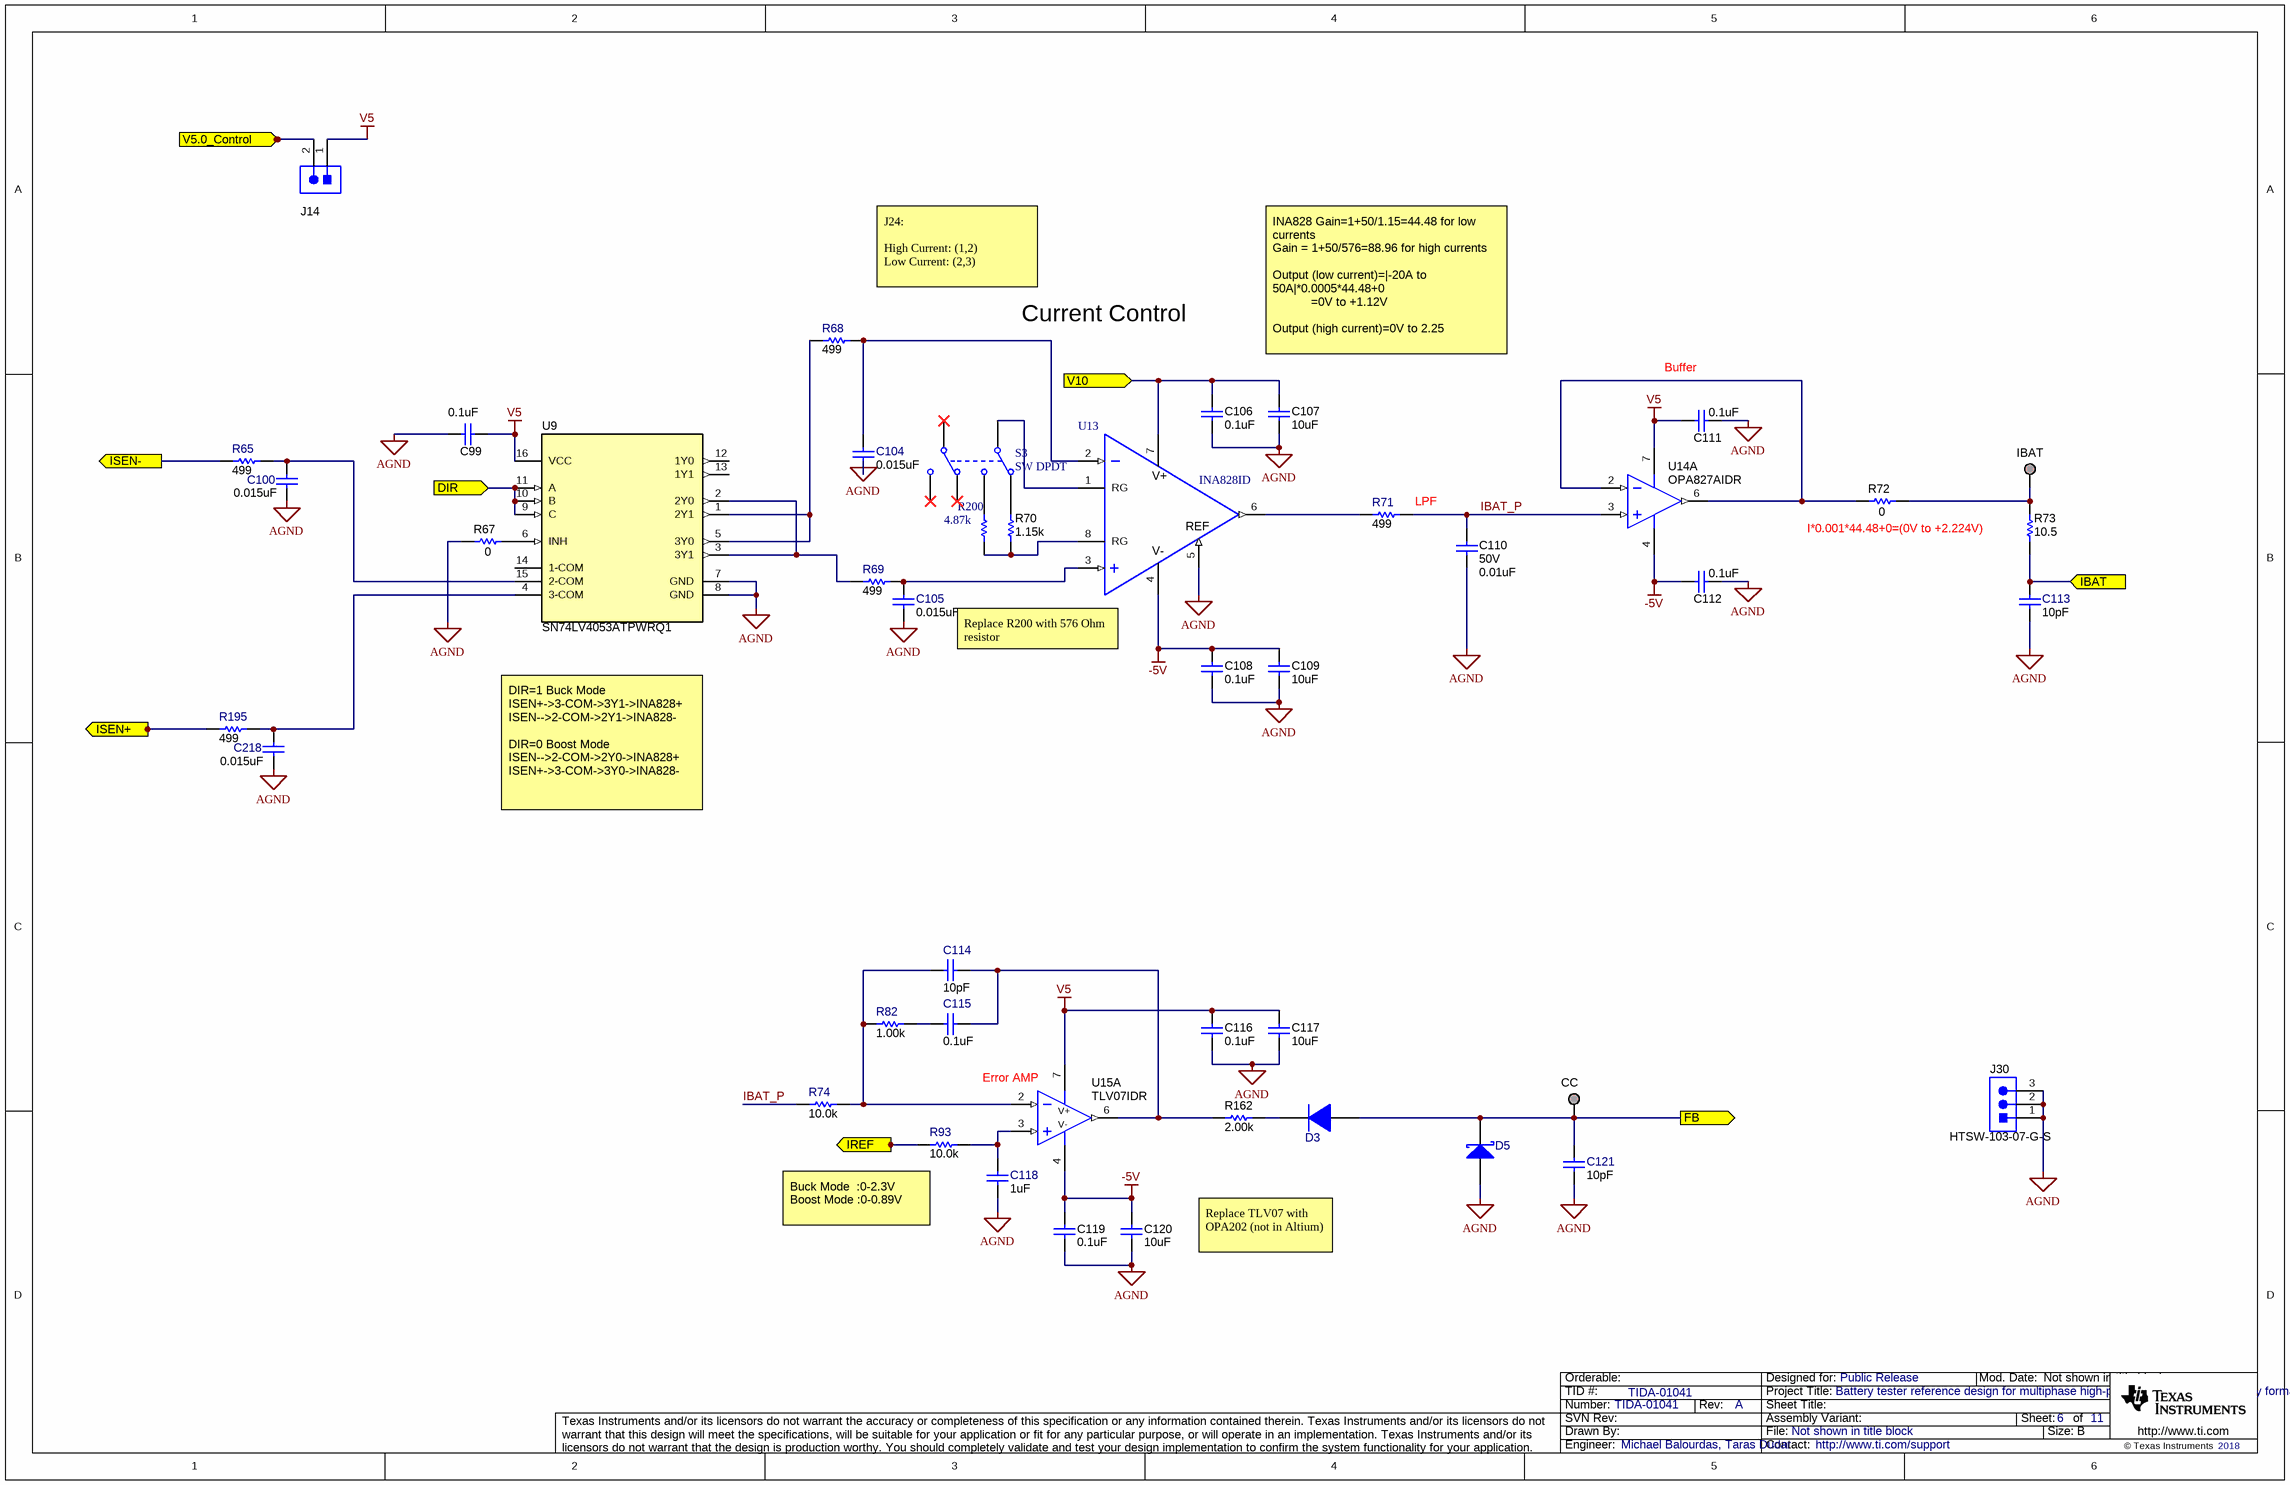
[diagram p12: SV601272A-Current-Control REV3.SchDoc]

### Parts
C99  ValueDisplayed: 0.1uF  [0603]  (hidden comment: Capacitor)
C100  ValueDisplayed: 0.015uF  [0603]  (hidden comment: Capacitor)
C104  ValueDisplayed: 0.015uF  [0603]  (hidden comment: Capacitor)
C105  ValueDisplayed: 0.015uF  [0603]  (hidden comment: Capacitor)
C106  ValueDisplayed: 0.1uF  [0603]  (hidden comment: Capacitor)
C107  ValueDisplayed: 10uF  [0805_HV]  (hidden comment: Capacitor)
C108  ValueDisplayed: 0.1uF  [0603]  (hidden comment: Capacitor)
C109  ValueDisplayed: 10uF  [0805_HV]  (hidden comment: Capacitor)
C110  VDC_V: 50V  ValueDisplayed: 0.01uF  [0603]  (hidden comment: GCM188R71H103KA37D)
C111  ValueDisplayed: 0.1uF  [0603]  (hidden comment: Capacitor)
C112  ValueDisplayed: 0.1uF  [0603]  (hidden comment: Capacitor)
C113  ValueDisplayed: 10pF  [0603]  (hidden comment: Capacitor)
C114  ValueDisplayed: 10pF  [0603]  (hidden comment: Capacitor)
C115  ValueDisplayed: 0.1uF  [0603]  (hidden comment: Capacitor)
C116  ValueDisplayed: 0.1uF  [0603]  (hidden comment: Capacitor)
C117  ValueDisplayed: 10uF  [0805_HV]  (hidden comment: Capacitor)
C118  ValueDisplayed: 1uF  [0603]  (hidden comment: Capacitor)
C119  ValueDisplayed: 0.1uF  [0603]  (hidden comment: Capacitor)
C120  ValueDisplayed: 10uF  [0805_HV]  (hidden comment: Capacitor)
C121  ValueDisplayed: 10pF  [0603]  (hidden comment: Capacitor)
C218  ValueDisplayed: 0.015uF  [0603]  (hidden comment: Capacitor)
CC  Pogo Pad  [PogoPad]  (value not drawn)  (no BOM)
D3  DIODE  [SOD-523]  (value not drawn)
D5  DIODE_SCHOTTKY  [SOD-323]  (value not drawn)
IBAT  Pogo Pad  [PogoPad]  (value not drawn)  (no BOM)
J14  HTSW-102-07-G-S  [Samtec_HTSW-102-07-G-S]  (value not drawn)
J30  HTSW-103-07-G-S  [Samtec_HTSW-103-07-G-S]
R65  ValueDisplayed: 499  [0603]  (hidden comment: Resistor)
R67  ValueDisplayed: 0  [0603]  (hidden comment: Resistor)
R68  ValueDisplayed: 499  [0603]  (hidden comment: Resistor)
R69  ValueDisplayed: 499  [0603]  (hidden comment: Resistor)
R70  1.15k  [0603]
R71  ValueDisplayed: 499  [0603]  (hidden comment: Resistor)
R72  ValueDisplayed: 0  [0603]  (hidden comment: Resistor)
R73  ValueDisplayed: 10.5  [0603]  (hidden comment: RC0603FR-0710R5L)
R74  ValueDisplayed: 10.0k  [0603]  (hidden comment: Resistor)
R82  ValueDisplayed: 1.00k  [0603]  (hidden comment: Resistor)
R93  ValueDisplayed: 10.0k  [0603]  (hidden comment: Resistor)
R162  ValueDisplayed: 2.00k  [0603]  (hidden comment: RT0603DRE072KL)
R195  ValueDisplayed: 499  [0603]  (hidden comment: Resistor)
R200  ValueDisplayed: 4.87k  [0603]  (hidden comment: RG1608P-4871-B-T5)
S3  SW DPDT  [SOT23-6_N]
U9  SN74LV4053ATPWRQ1  [PW0016A_L]
U13  INA828ID  [D0008A_N]
U14  OPA827AIDR  [D0008A_L]  (part A of 2)
U15  TLV07IDR  [D0008A_N]  (part A of 2)

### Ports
DIR, FB, IBAT, IREF, ISEN+, ISEN-, V5.0_Control, V10

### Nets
-5V: C108.1 C109.1 C112.1 C119.1 C120.1 U13.4(V-) U14.4(V-) U15.4(V-)
AGND: C99.1 C100.2 C104.2 C105.2 C106.2 C107.2 C108.2 C109.2 C110.2 C111.2 C112.2 C113.1 C116.2 C117.2 C118.1 C119.2 C120.2 C121.1 C218.2 D5.2(A) J30.1 J30.2 J30.3 R67.1 U9.7(GND) U9.8(GND) U13.5(REF)
V5: C99.2 C111.1 C116.1 C117.1 J14.1 U9.16(VCC) U14.7(V+) U15.7(V+)
VCC: C106.1 C107.1 U13.7(V+) ; port V10
DIR: U9.9(C) U9.10(B) U9.11(A) ; port DIR
FB: C121.2 CC.1 D3.2(A) D5.1(K) ; port FB
IBAT: C113.2 R73.1 ; port IBAT
IBAT_P: C110.1 R71.1 R74.1 U14.3(IN+)
IREF: R93.1 ; port IREF
ISEN+: R195.2 ; port ISEN+
ISEN-: R65.2 ; port ISEN-
V5.0_Control: J14.2 ; port V5.0_Control
NetC100_1: C100.1 R65.1 U9.15(2-COM)
NetC104_1: C104.1 R68.1 U13.2(IN-)
NetC105_1: C105.1 R69.1 U13.3(IN+)
NetC114_1: C114.1 R74.2 R82.1 U15.2(IN-)
NetC114_2: C114.2 C115.1 R162.1 U15.6(OUT)
NetC115_2: C115.2 R82.2
NetC118_2: C118.2 R93.2 U15.3(IN+)
NetC218_1: C218.1 R195.1 U9.4(3-COM)
NetD3_1: D3.1(K) R162.2
NetIBAT_1: IBAT.1 R72.2 R73.2
NetR67_2: R67.2 U9.6(INH)
NetR68_2: R68.2 U9.1(2Y1) U9.5(3Y0)
NetR69_2: R69.2 U9.2(2Y0) U9.3(3Y1)
NetR70_1: R70.1 R200.1 U13.8(RG)
NetR70_2: R70.2 S3.2(NC1)
NetR71_2: R71.2 U13.6(OUT)
NetR72_1: R72.1 U14.2(IN-) U14.6(OUT)
NetR200_2: R200.2 S3.3(NO1)
NetS3_1: S3.1(COMMON1) U13.1(RG)

Not connected (* = marked no-connect by the designer): S3 4(NC2)* 5(COMMON2)* 6(NO2)*; U9 12(1Y0) 13(1Y1) 14(1-COM)

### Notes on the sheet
- J24:
  High Current: (1,2)
  Low Current: (2,3)
- Current Control
- INA828 Gain=1+50/1.15=44.48 for low currents
  Gain = 1+50/576=88.96 for high currents
  Output (low current)=|-20A to 50A|*0.0005*44.48+0
  =0V to +1.12V
  Output (high current)=0V to 2.25
- (near C111) Buffer
- (near R71) LPF
- (near R72) I*0.001*44.48+0=(0V to +2.224V)
- Replace R200 with 576 Ohm resistor
- DIR=1 Buck Mode
  ISEN+->3-COM->3Y1->INA828+
  ISEN-->2-COM->2Y1->INA828-
  DIR=0 Boost Mode
  ISEN-->2-COM->2Y0->INA828+
  ISEN+->3-COM->3Y0->INA828-
- (near U15) Error AMP
- (near R93) Buck Mode  :0-2.3V
  Boost Mode :0-0.89V
- Replace TLV07 with OPA202 (not in Altium)

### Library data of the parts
C99 C106 C108 C111 C112 C116 C119 = CMP-0006752-5: CAP, CERM, 0.1 uF, 25 V, +/- 5%, X7R, 0603; PartNumber: 06033C104JAT2A; Manufacturer: AVX; Polarized: N; Value: 0.1uF; U/M: EA; Cap_F: 100nF; ESR_ohm: 0.05; Value1: 0.05 ohm; VDC_V: 25V; TaMin_C: -55°C; TaMax_C: 125°C; AEC Category: Q200; SizeArea_mm2: 1.28; SizeAreaWB_mm2: 4.68; SizeX_mm: 1.6; SizeY_mm: 0.8; SizeZ_mm: 1
C100 C104 C105 C218 = CMP-0007383-5: CAP, CERM, 0.015 uF, 16 V, +/- 10%, X7R, 0603; PartNumber: GRM188R71C153KA01D; Manufacturer: MuRata; Polarized: N; U/M: EA; Cap_F: 15nF; Value1: Unknown; VDC_V: 16V; TaMin_C: -55°C; TaMax_C: 125°C; SizeArea_mm2: 1.28; SizeAreaWB_mm2: 4.68; SizeX_mm: 1.6; SizeY_mm: 0.8; SizeZ_mm: 1; AEC Category: Q200
C107 C109 C117 C120 = CMP-0008315-2: CAP, CERM, 10 uF, 10 V, +/- 10%, X7R, 0805; PartNumber: GRM21BR71A106KE51L; Manufacturer: MuRata; Polarized: N; Value: 10uF; U/M: EA; Cap_F: 10µF; ESR_ohm: 3m; Value1: 0.003 ohm; VDC_V: 10V; TaMin_C: -55°C; TaMax_C: 125°C; Cap_Case: 0805; AEC Category: Q200; SizeArea_mm2: 2.5; SizeAreaWB_mm2: 6.75; SizeX_mm: 2; SizeY_mm: 1.25; SizeZ_mm: 1.45
C110 = CMP-0007143-4: CAP, CERM, 0.01 uF, 50 V, +/- 10%, X7R, AEC-Q200 Grade 1, 0603; Manufacturer: MuRata; TaMin_C: -55°C; Polarized: N; SizeAreaWB_mm2: 4.68; Value1: Unknown; U/M: EA; Value: 0.01uF; TaMax_C: 125°C; SizeZ_mm: 1; SizeX_mm: 1.6; SizeY_mm: 0.8; SizeArea_mm2: 1.28; CompType: Capacitor; AEC Qualified: Y; Cap_F: 10nF; AEC Category: Q200
C113 C114 C121 = CMP-0007170-4: CAP, CERM, 10 pF, 50 V, +/- 5%, C0G/NP0, 0603; PartNumber: GRM1885C1H100JA01D; Manufacturer: MuRata; Polarized: N; Value: 10pF; U/M: EA; Value1: Unknown; VDC_V: 50V; TaMin_C: -55°C; TaMax_C: 125°C; SizeArea_mm2: 1.28; SizeAreaWB_mm2: 4.68; SizeX_mm: 1.6; SizeY_mm: 0.8; SizeZ_mm: 1; AEC Category: Q200
C115 = CMP-0007334-5: CAP, CERM, 0.1 uF, 16 V, +/- 10%, X5R, 0603; PartNumber: GRM188R61C104KA01D; Manufacturer: MuRata; Polarized: N; Value: 0.1uF; U/M: EA; Cap_F: 100nF; Value1: Unknown; VDC_V: 16V; TaMin_C: -55°C; TaMax_C: 85°C; SizeArea_mm2: 1.28; SizeAreaWB_mm2: 4.68; SizeX_mm: 1.6; SizeY_mm: 0.8; SizeZ_mm: 1; AEC Category: Q200
C118 = CMP-0007302-5: CAP, CERM, 1 uF, 6.3 V, +/- 10%, X5R, 0603; PartNumber: GRM188R60J105KA01D; Manufacturer: MuRata; Polarized: N; Value: 1uF; U/M: EA; Cap_F: 1µF; Value1: Unknown; VDC_V: 6.3V; TaMin_C: -55°C; TaMax_C: 85°C; SizeArea_mm2: 1.28; SizeAreaWB_mm2: 4.68; SizeX_mm: 1.6; SizeY_mm: 0.8; SizeZ_mm: 1; AEC Category: Q200
CC IBAT = PogoPad: as V-5 on sheet SV601272A-Bias
D3 = CMP-0076957-2: Diode, Switching, 75 V, 0.3 A, SOD-523; PartNumber: 1N4148X-TP; Manufacturer: Micro Commercial Components; U/M: EA; Vf_V: 1.25V; Value: 75V; Value1: 0.3A; Io_A: 3dA; TJmax_C: 150°C; SizeAreaWB_mm2: 5.13; SizeArea_mm2: 1.53; SizeX_mm: 1.7; SizeY_mm: 0.9; SizeZ_mm: 0.65; AEC Category: Q101; Green_Lifecycle: Not Set; Green_REACh: Incomplete
D5 = CMP-0028458-1: Diode, Schottky, 30 V, 0.2 A, SOD-323; PartNumber: BAT54WS-7-F; Manufacturer: Diodes Inc.; U/M: EA; Vf_V: 7dV; Value: 30V; Value1: 0.2A; Value2: 0.7V; Io_A: 2dA; TJmax_C: 125°C; SizeAreaWB_mm2: 8.695; SizeArea_mm2: 3.645; SizeX_mm: 2.7; SizeY_mm: 1.35; SizeZ_mm: 1; AEC Category: Q101; Green_Lifecycle: Active; Green_REACh: Passed
J14 = HTSW-102-07-G-S: as J3 on sheet SV601272A-Controller1
J30 = HTSW-103-07-G-S: as J1 on sheet SV601272A-Controller1
R65 R68 R69 R71 R195 = CMP-0022446-5: RES, 499, 1%, 0.1 W, AEC-Q200 Grade 0, 0603; PartNumber: CRCW0603499RFKEA; Manufacturer: Vishay-Dale; Value: 499; Value_Code: 499R; Power_W: 100mW; Value2: 0.1W; VDC_V: 75V; TempCo: 100 ppm/C; SizeArea_mm2: 1.28; SizeX_mm: 1.6; SizeY_mm: 0.8; SizeZ_mm: 1; EIA_Code: E96; AEC Category: Q200; AEC Qualified: Y; AEC Grade: 0
R67 R72 = CMP-0025874-3: as R160 on sheet SV601272A-Controller1
R70 = CMP-0023872-3: RES, 1.15 k, 0.1%, 0.1 W, 0603; Manufacturer: Yageo America; PartNumber: RT0603BRD071K15L; Power_W: 100mW; TempCo: 25 ppm/C; Value_Code: 1k15; U/M: EA; EIA_Code: E192; SizeX_mm: 1.6; SizeY_mm: 0.8; SizeZ_mm: 1; SizeArea_mm2: 1.28; CompType: Resistor; Value2: 0.1W; VDC_V: 75V; AEC Category: Q200
R73 = CMP-0022749-2: RES, 10.5, 1%, 0.1 W, 0603; Manufacturer: Yageo America; Power_W: 100mW; TempCo: 200 ppm/C; Value_Code: 10R5; U/M: EA; Value: 10.5; EIA_Code: E96; SizeX_mm: 1.6; SizeY_mm: 0.8; SizeZ_mm: 1; Value2: 0.1W; SizeArea_mm2: 1.28; CompType: Resistor; VDC_V: 150V; AEC Category: Q200
R74 R93 = CMP-0022746-3: RES, 10.0 k, 1%, 0.1 W, 0603; PartNumber: RC0603FR-0710KL; Manufacturer: Yageo America; Value: 10.0k; Res_ohm: 10k; Value_Code: 10k0; Power_W: 100mW; Value2: 0.1W; VDC_V: 150V; TempCo: 200 ppm/C; SizeArea_mm2: 1.28; SizeX_mm: 1.6; SizeY_mm: 0.8; SizeZ_mm: 1; EIA_Code: E96; U/M: EA; AEC Category: Q200
R82 = CMP-0022895-3: RES, 1.00 k, 1%, 0.1 W, 0603; PartNumber: RC0603FR-071KL; Manufacturer: Yageo America; Value: 1.00k; Res_ohm: 1k; Value_Code: 1k00; Power_W: 100mW; Value2: 0.1W; VDC_V: 150V; TempCo: 200 ppm/C; SizeArea_mm2: 1.28; SizeX_mm: 1.6; SizeY_mm: 0.8; SizeZ_mm: 1; EIA_Code: E96; U/M: EA; AEC Category: Q200
R162 = CMP-0025080-3: RES, 2.00 k, 0.5%, 0.1 W, 0603; Manufacturer: Yageo America; Power_W: 100mW; TempCo: 50 ppm/C; Value_Code: 2k00; U/M: EA; Value: 2.00k; EIA_Code: E192; Res_ohm: 2k; SizeX_mm: 1.6; SizeY_mm: 0.8; SizeZ_mm: 1; Value2: 0.1W; SizeArea_mm2: 1.28; CompType: Resistor; VDC_V: 75V; AEC Category: Q200
R200 = CMP-0023560-3: RES, 4.87 k, 0.1%, 0.1 W, 0603; Manufacturer: Susumu Co Ltd; Power_W: 100mW; TempCo: 25 ppm/C; Value_Code: 4k87; U/M: EA; Value: 4.87k; EIA_Code: E192; SizeX_mm: 1.6; SizeY_mm: 0.8; SizeZ_mm: 1; Value2: 0.1W; SizeArea_mm2: 1.28; VDC_V: 75V; AEC Category: Q200
S3 = SW DPDT: Switch
U9 = CMP-0076549-1: TRIPLE 2-CHANNEL ANALOG MULTIPLEXER/DEMULTIPLEXER, PW0016A (TSSOP-16); Manufacturer: Texas Instruments; SizeAreaWB_mm2: 58.8; SizeArea_mm2: 32.0; SizeZ_mm: 1.2; SizeY_mm: 5.0; U/M: EA; CompType: IC; SizeX_mm: 6.4
U13 = CMP-0079943-1: 50-uV Offset, 7-nV/√Hz Noise, Low-Power, Precision Instrumentation Amplifier, D0008A (SOIC-8); Alternate PartNumber: INA828IDR; Alternate Manufacturer: Texas Instruments; SizeAreaWB_mm2: 56.58; SizeZ_mm: 1.75; SizeX_mm: 4.9; SizeY_mm: 6.2; SizeArea_mm2: 30.38; CompType: IC; AEC Qualified: N; AEC Category: Q200
U14 = CMP-0041267-2: Low-Noise, High-Precision, JFET-Input Operational Amplifier, 8 to 36 V, -40 to 125 degC, 8-pin SOIC (D8), Green (RoHS & no Sb/Br); Manufacturer: Texas Instruments; Vmax(V): 36; GBW(Typ)(MHz): 22; Vmin(V): 8; Iq per channel(Max)(mA): 5.2; SubFamily: Audio Operational Amplifier; Number of Channels: 1; Vn at Flatband(Typ)(nV/rtHz): 4
U15 = CMP-0079847-1: 36-V Precision, Rail-to-Rail Output, Operational Amplifier, D0008A (SOIC-8); Alternate Manufacturer: Texas Instruments; SizeAreaWB_mm2: 56.58; SizeZ_mm: 1.75; SizeX_mm: 4.9; SizeY_mm: 6.2; SizeArea_mm2: 30.38; CompType: IC; AEC Qualified: N; AEC Category: Q200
